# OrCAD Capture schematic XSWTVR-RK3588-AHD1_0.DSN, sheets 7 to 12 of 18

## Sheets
7 06 AHD-NVP6188A-05-08: size Custom; note: 06 AHD-NVP6188A
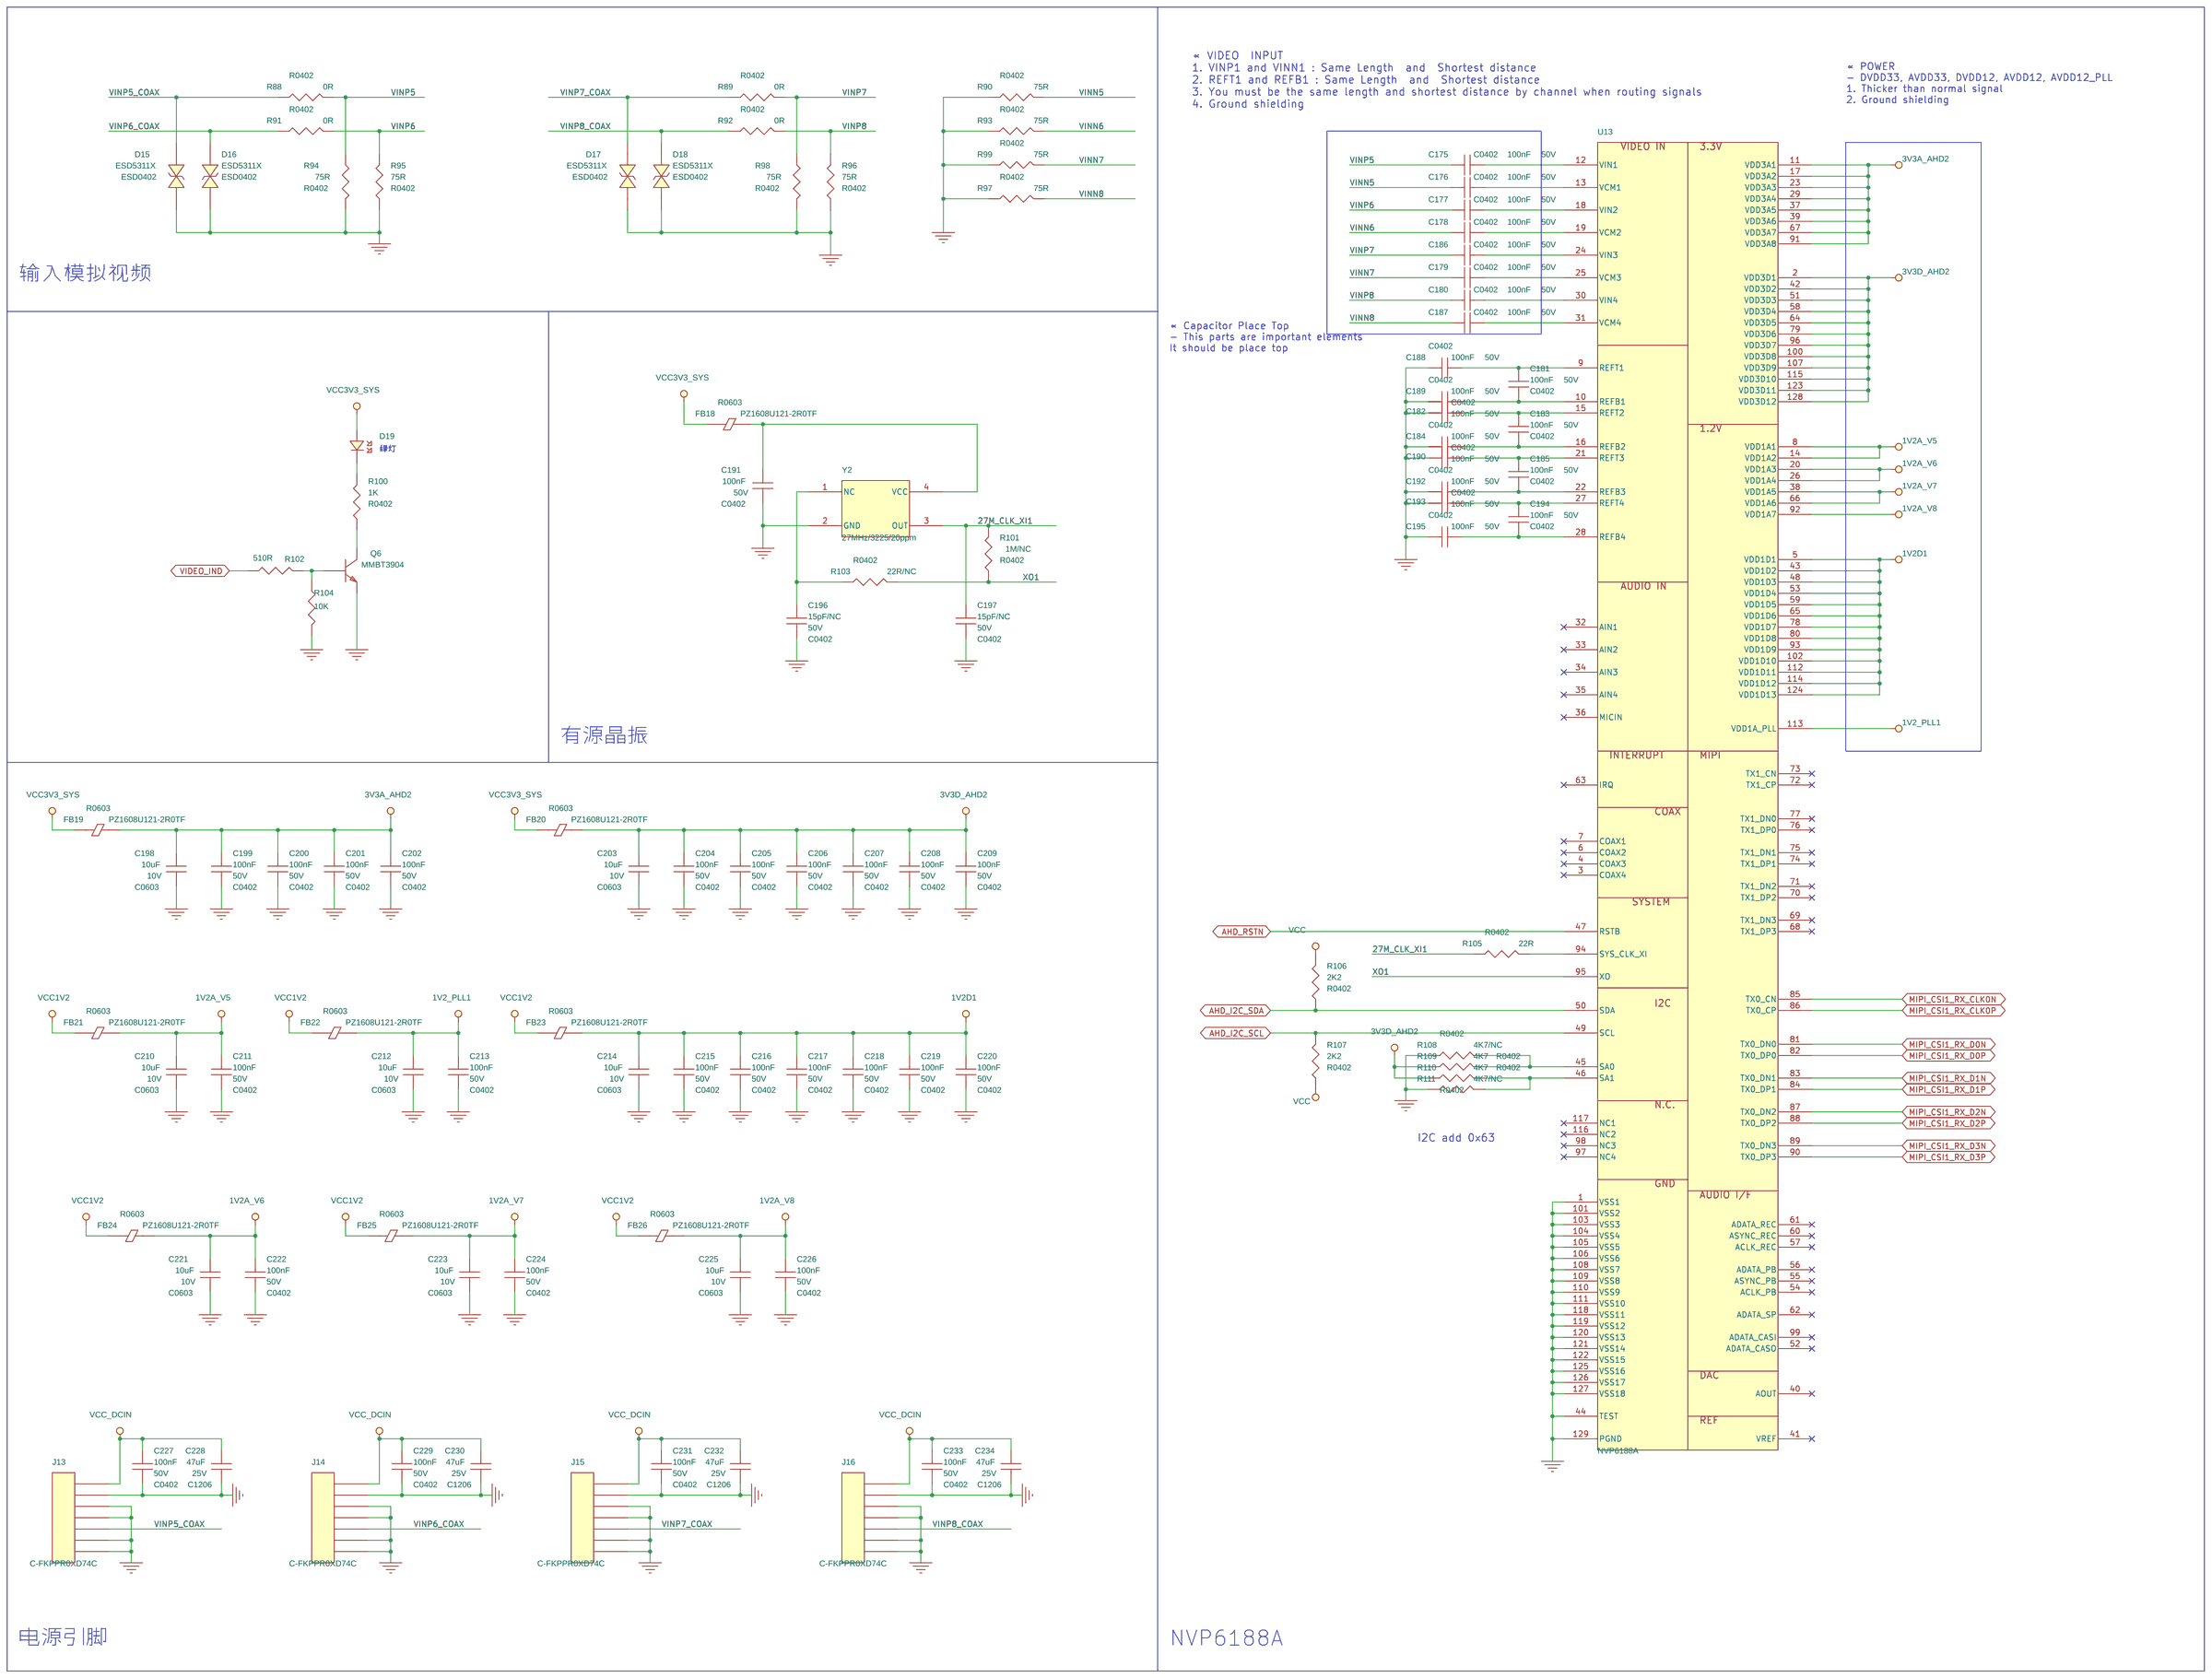
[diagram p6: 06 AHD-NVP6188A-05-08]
8 07 HDMI OUT: size A3; note: 07 HDMI OUT
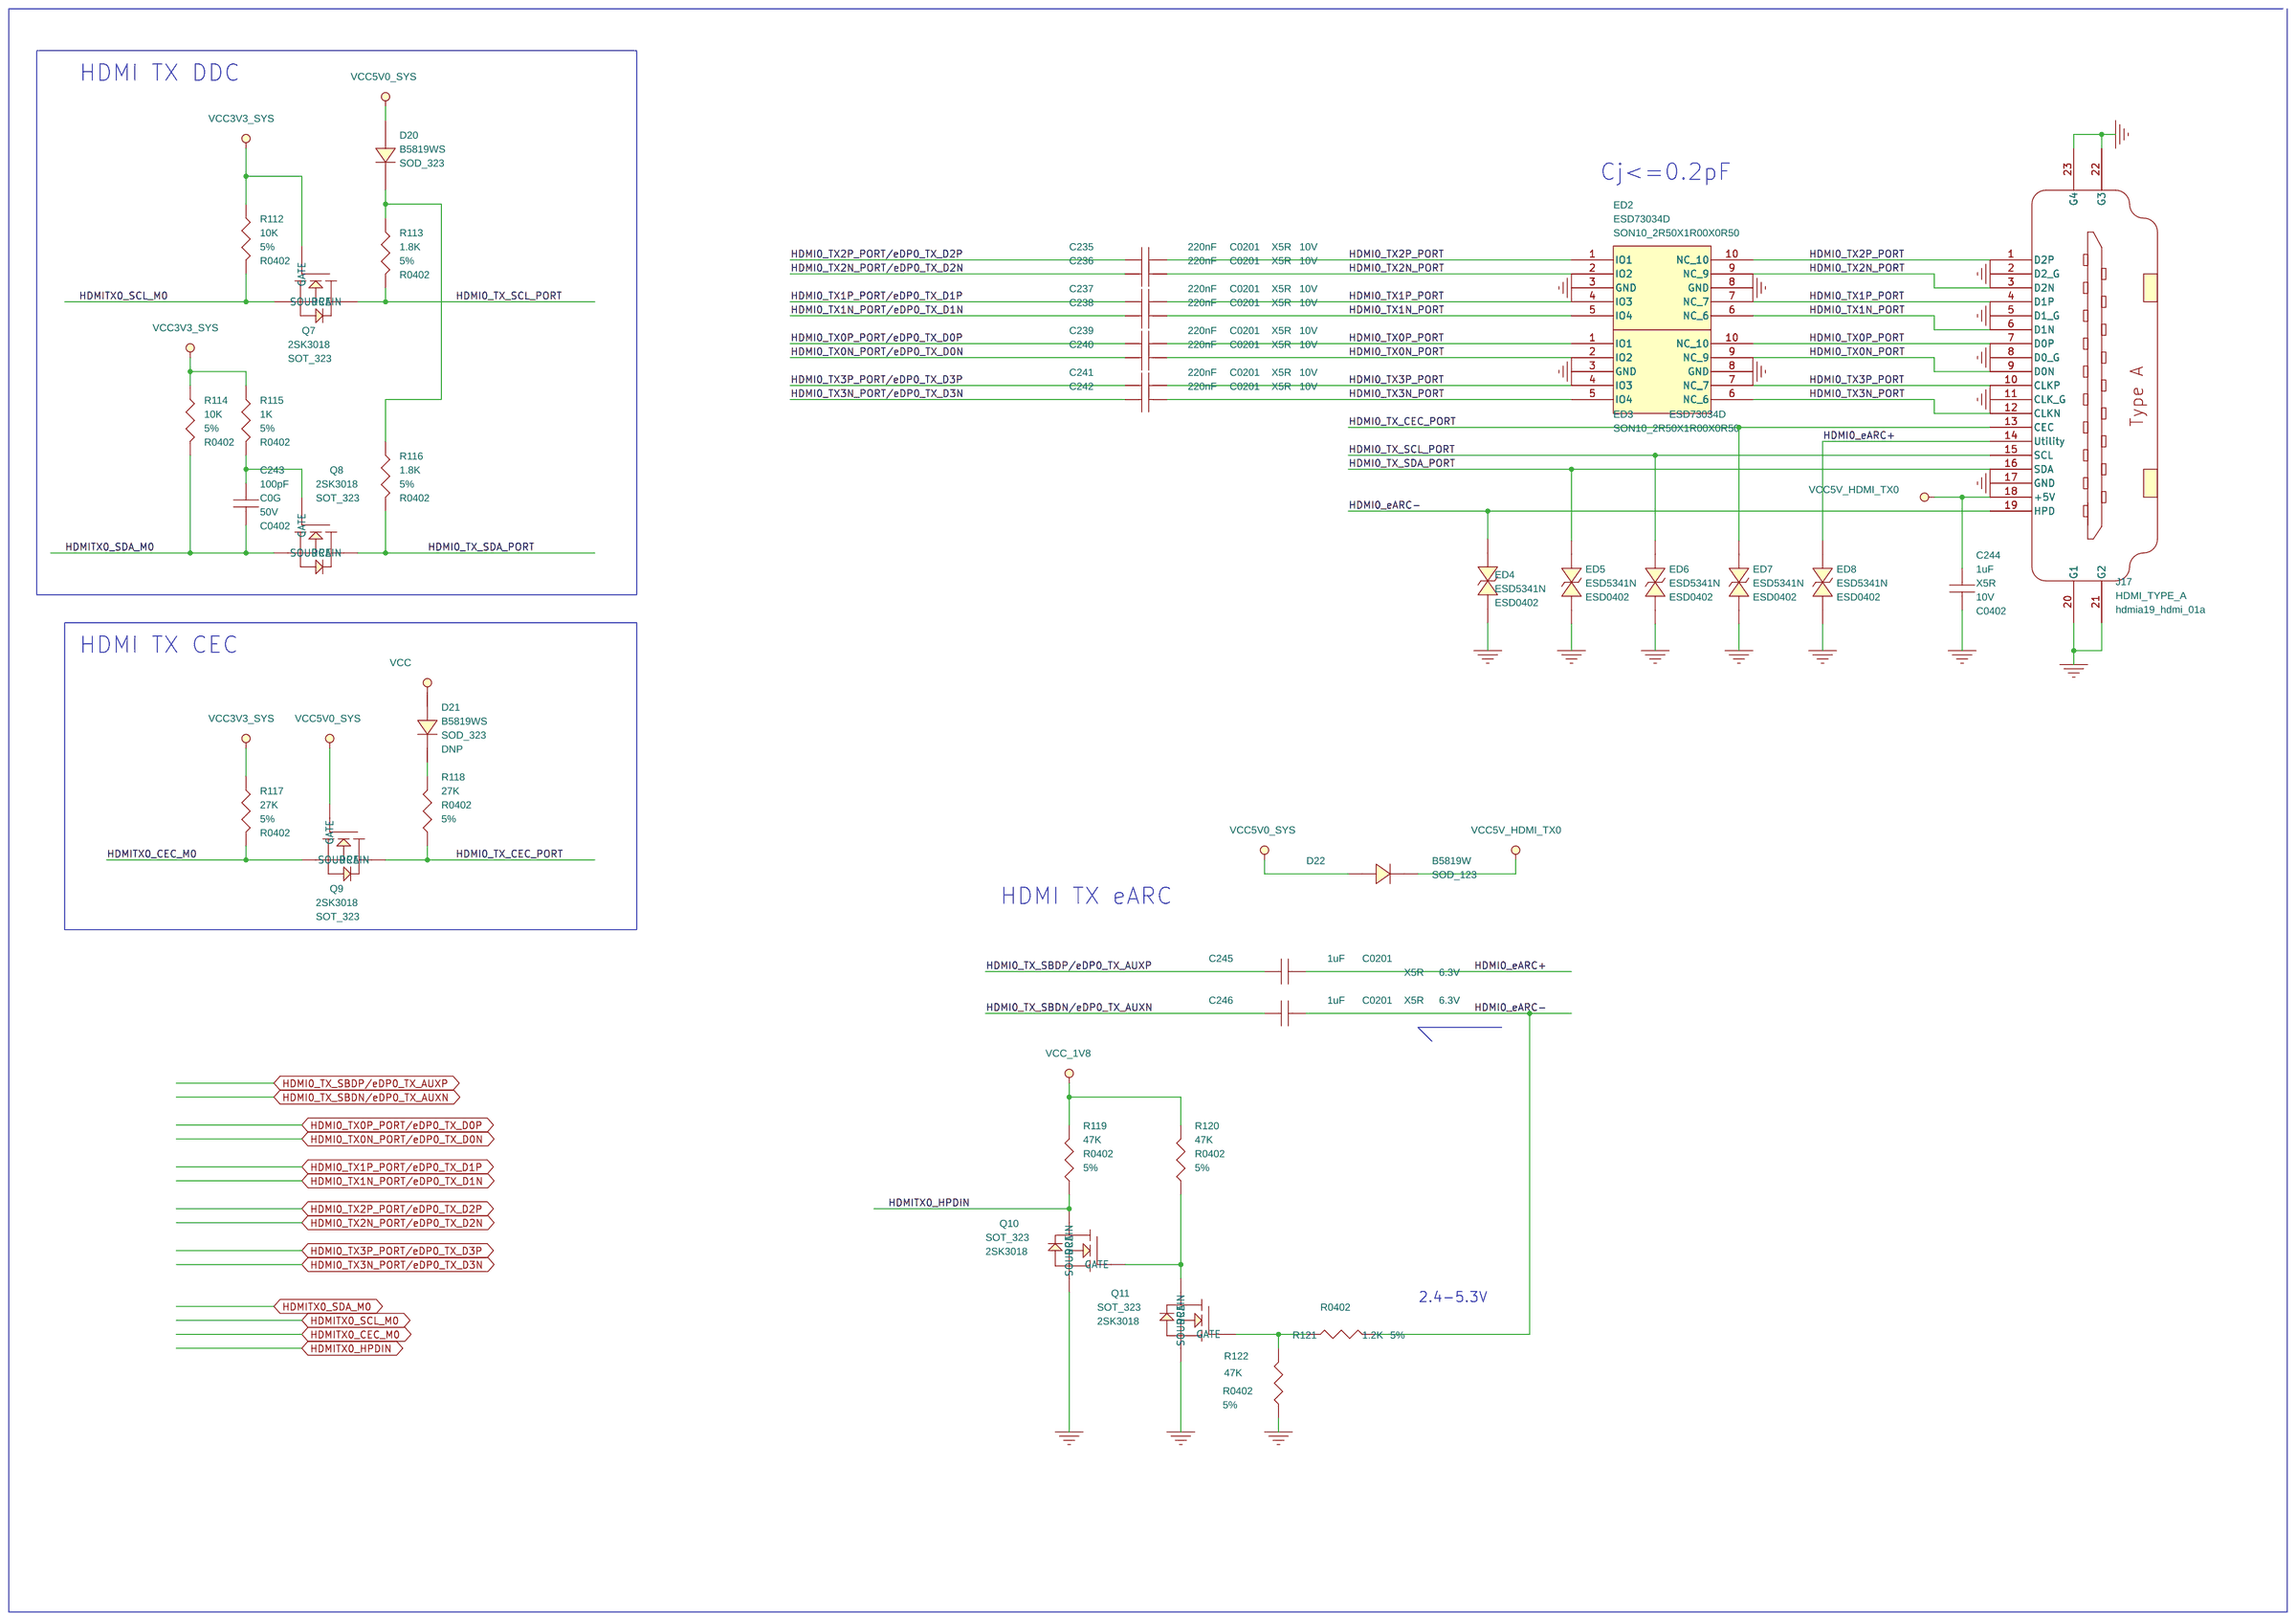
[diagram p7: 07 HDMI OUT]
9 08 WIFI6&GNSS: size Custom; note: 08 WIFI6&GNSS
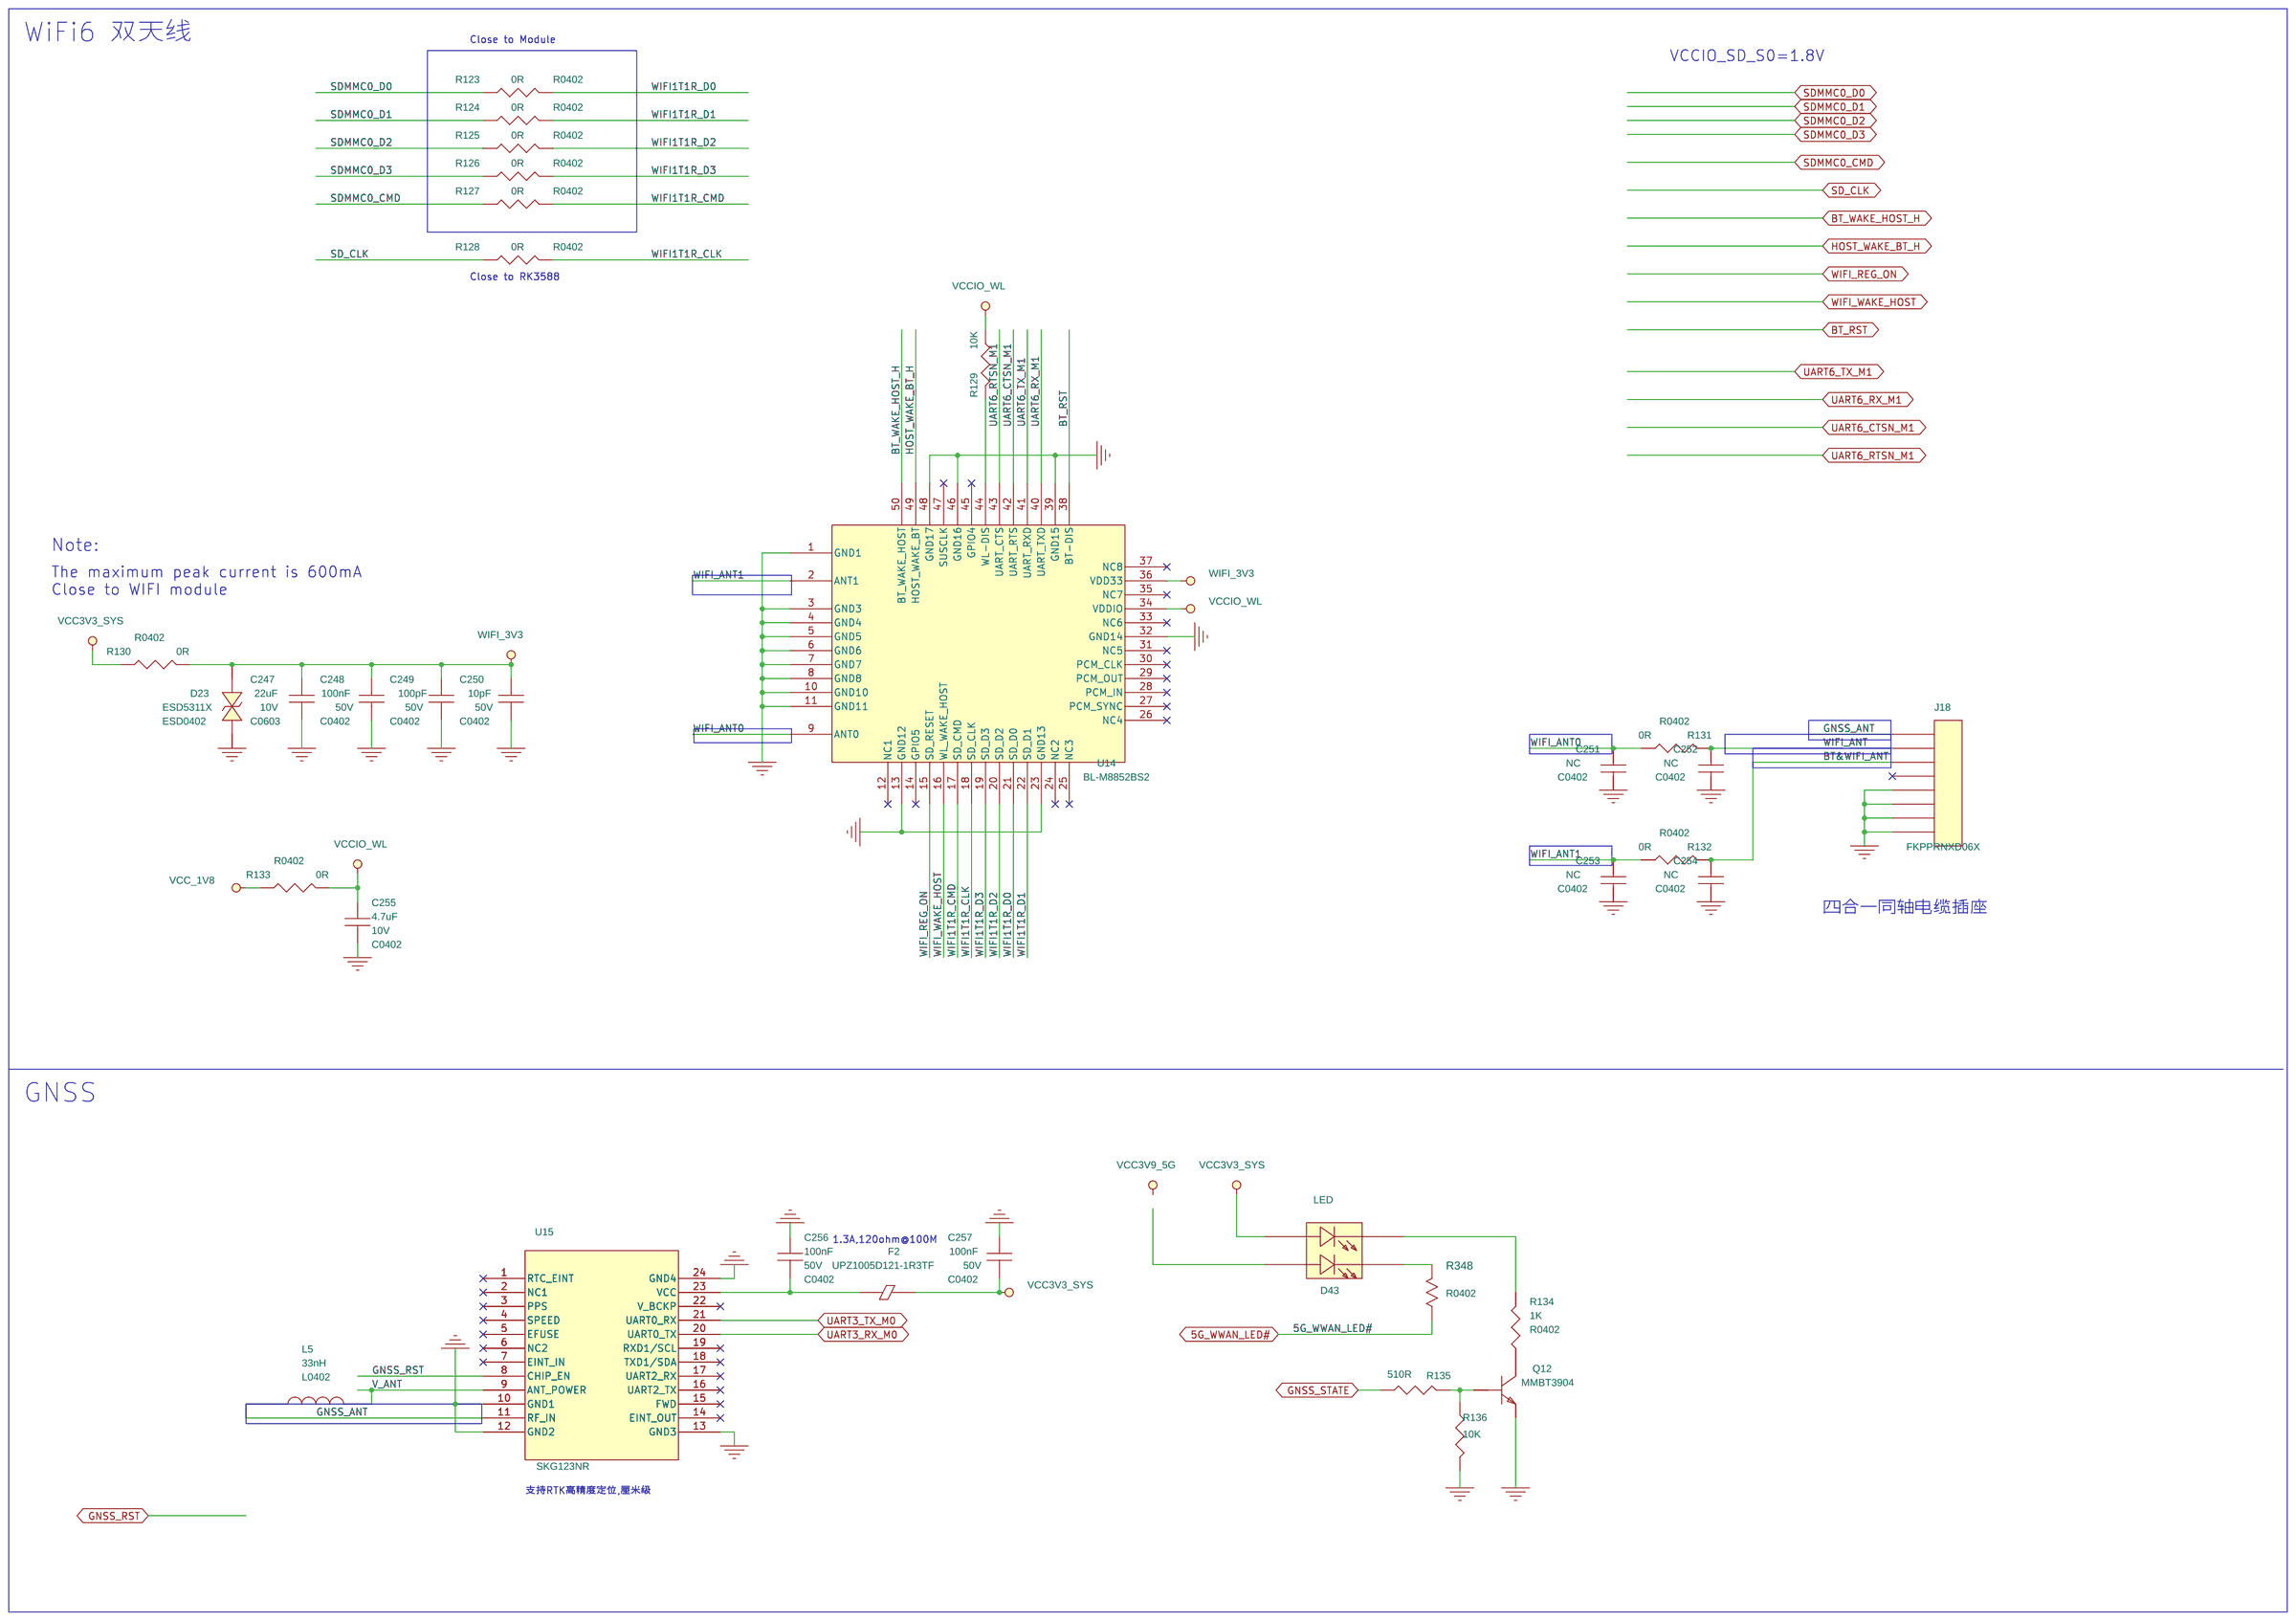
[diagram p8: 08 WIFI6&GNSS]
10 09 Ethernet-GPHY_RGMI0: size A3; rev: V1.0; note: 09 Ethernet-GPHY_RGMI0
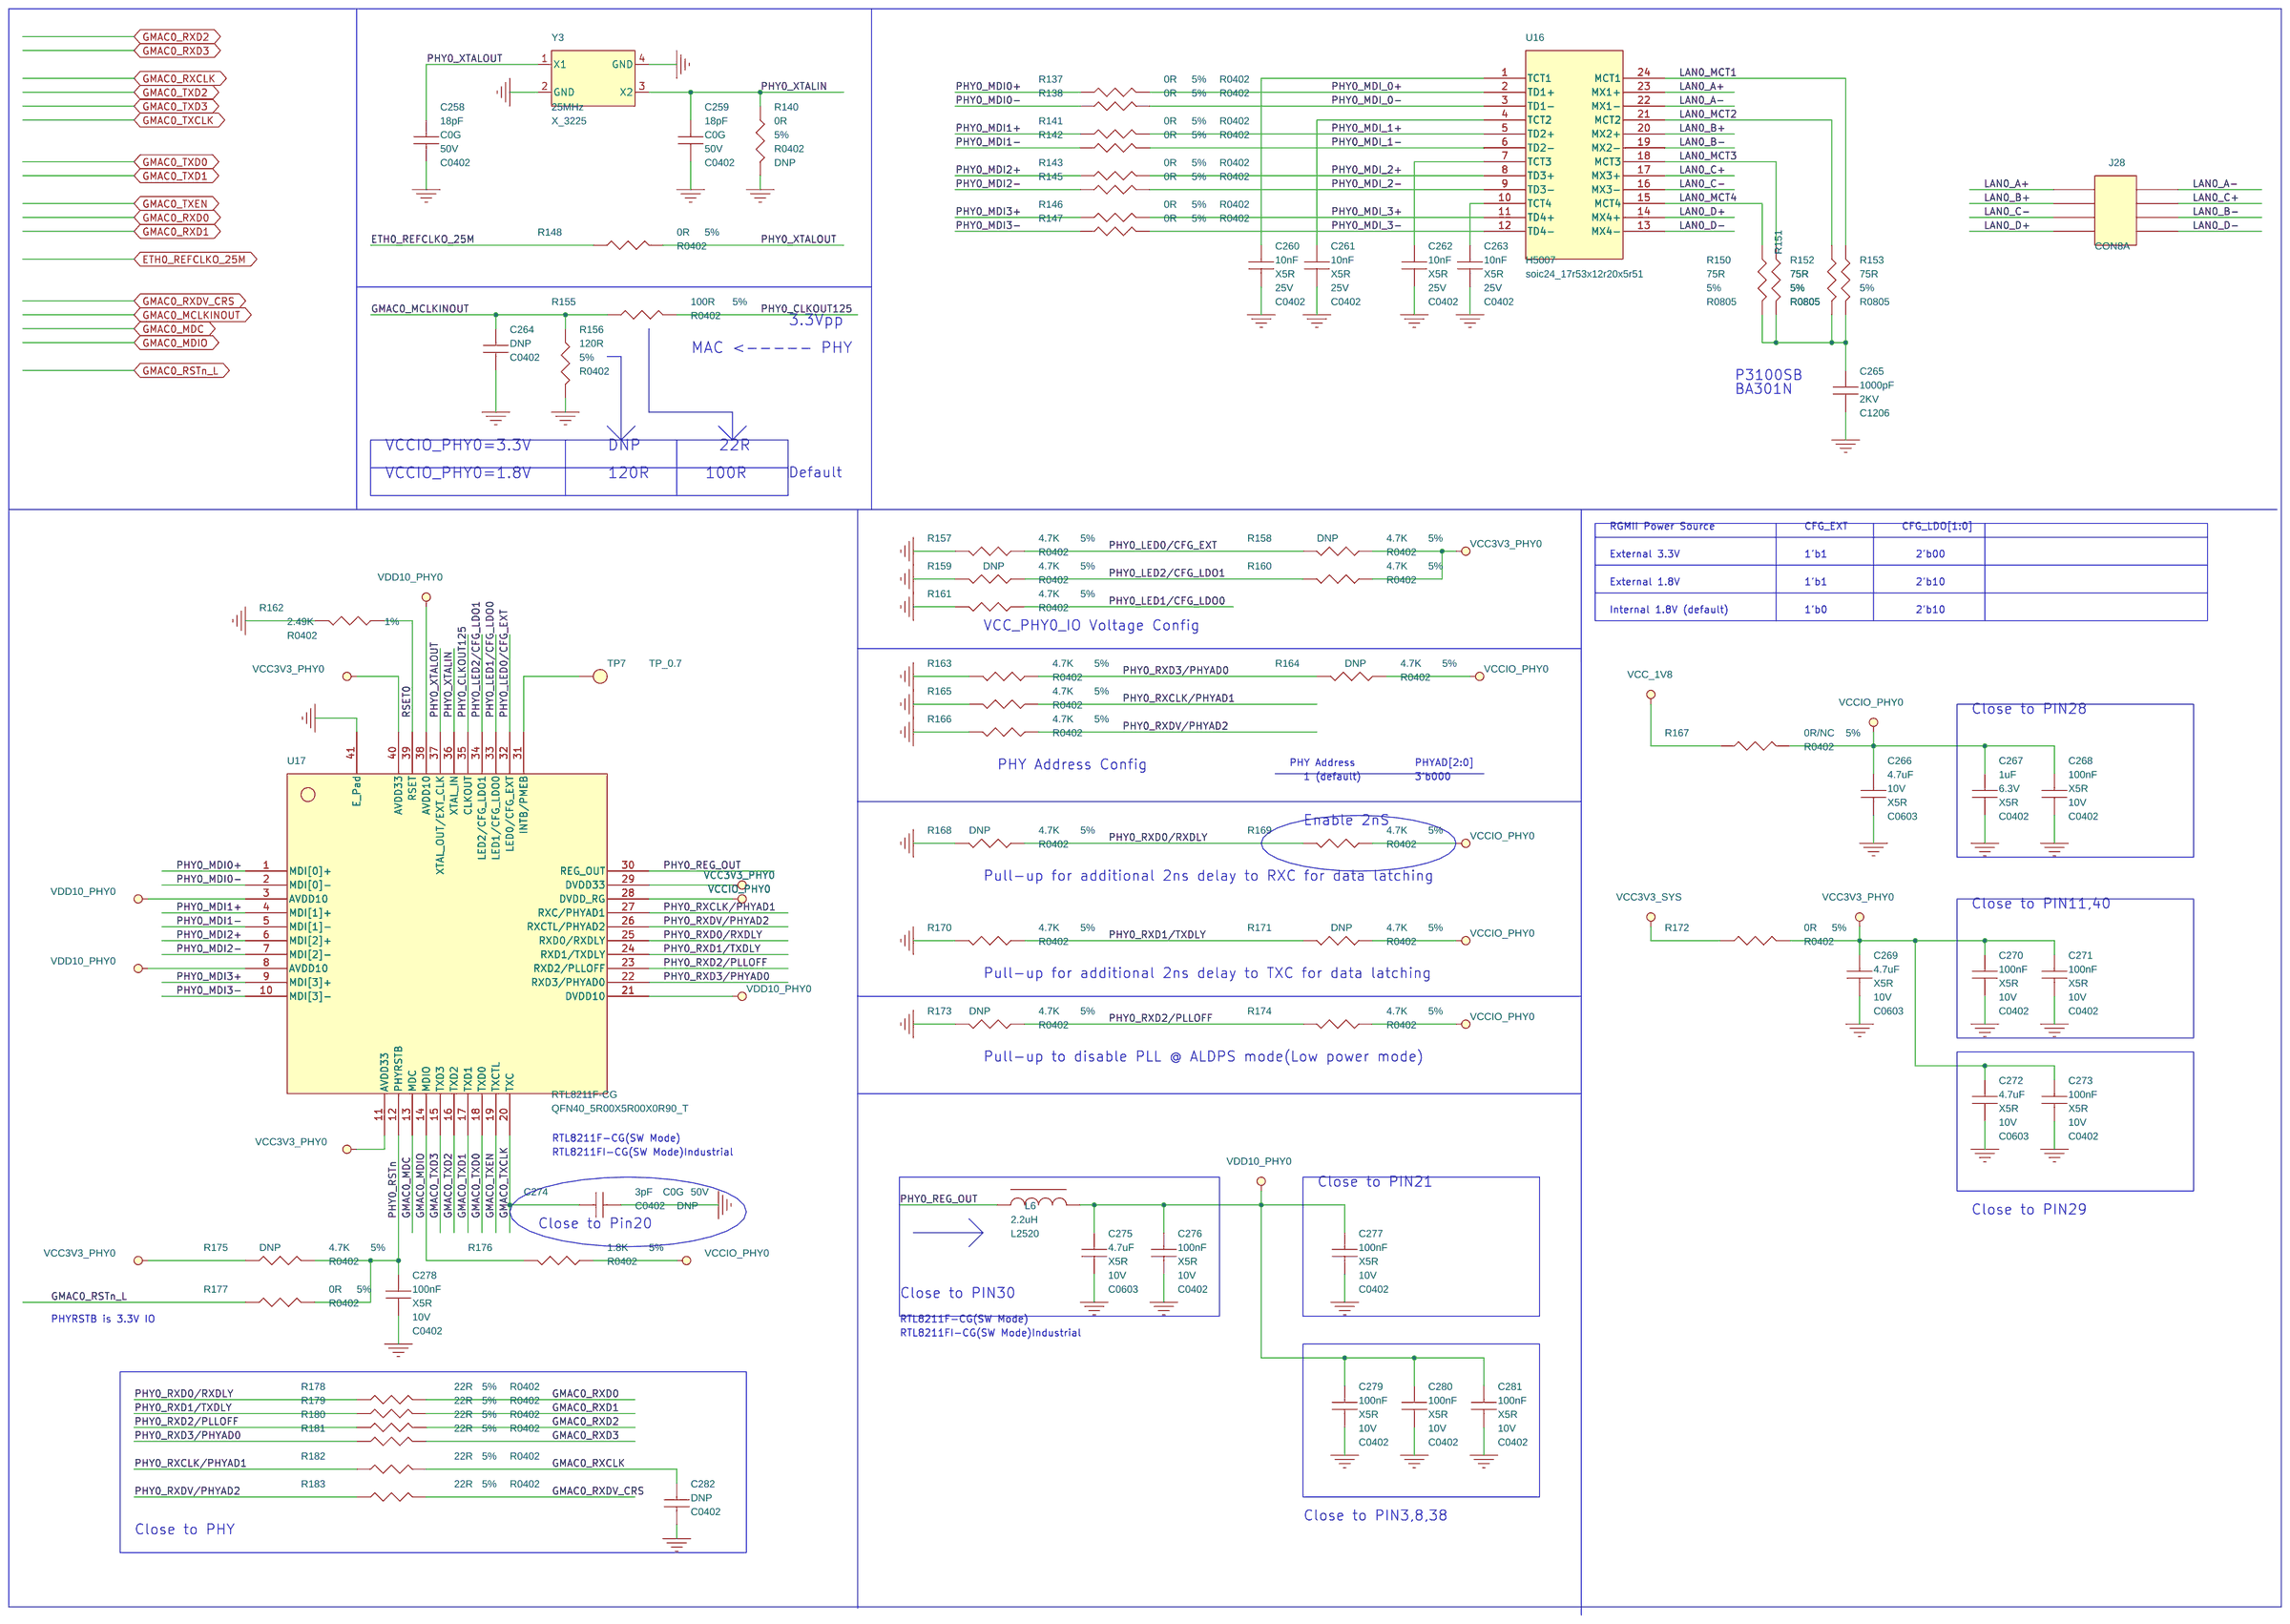
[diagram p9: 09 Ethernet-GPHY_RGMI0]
11 10 Ethernet-GPHY_RGMI1: size A3; note: 10 Ethernet-GPHY_RGMI1
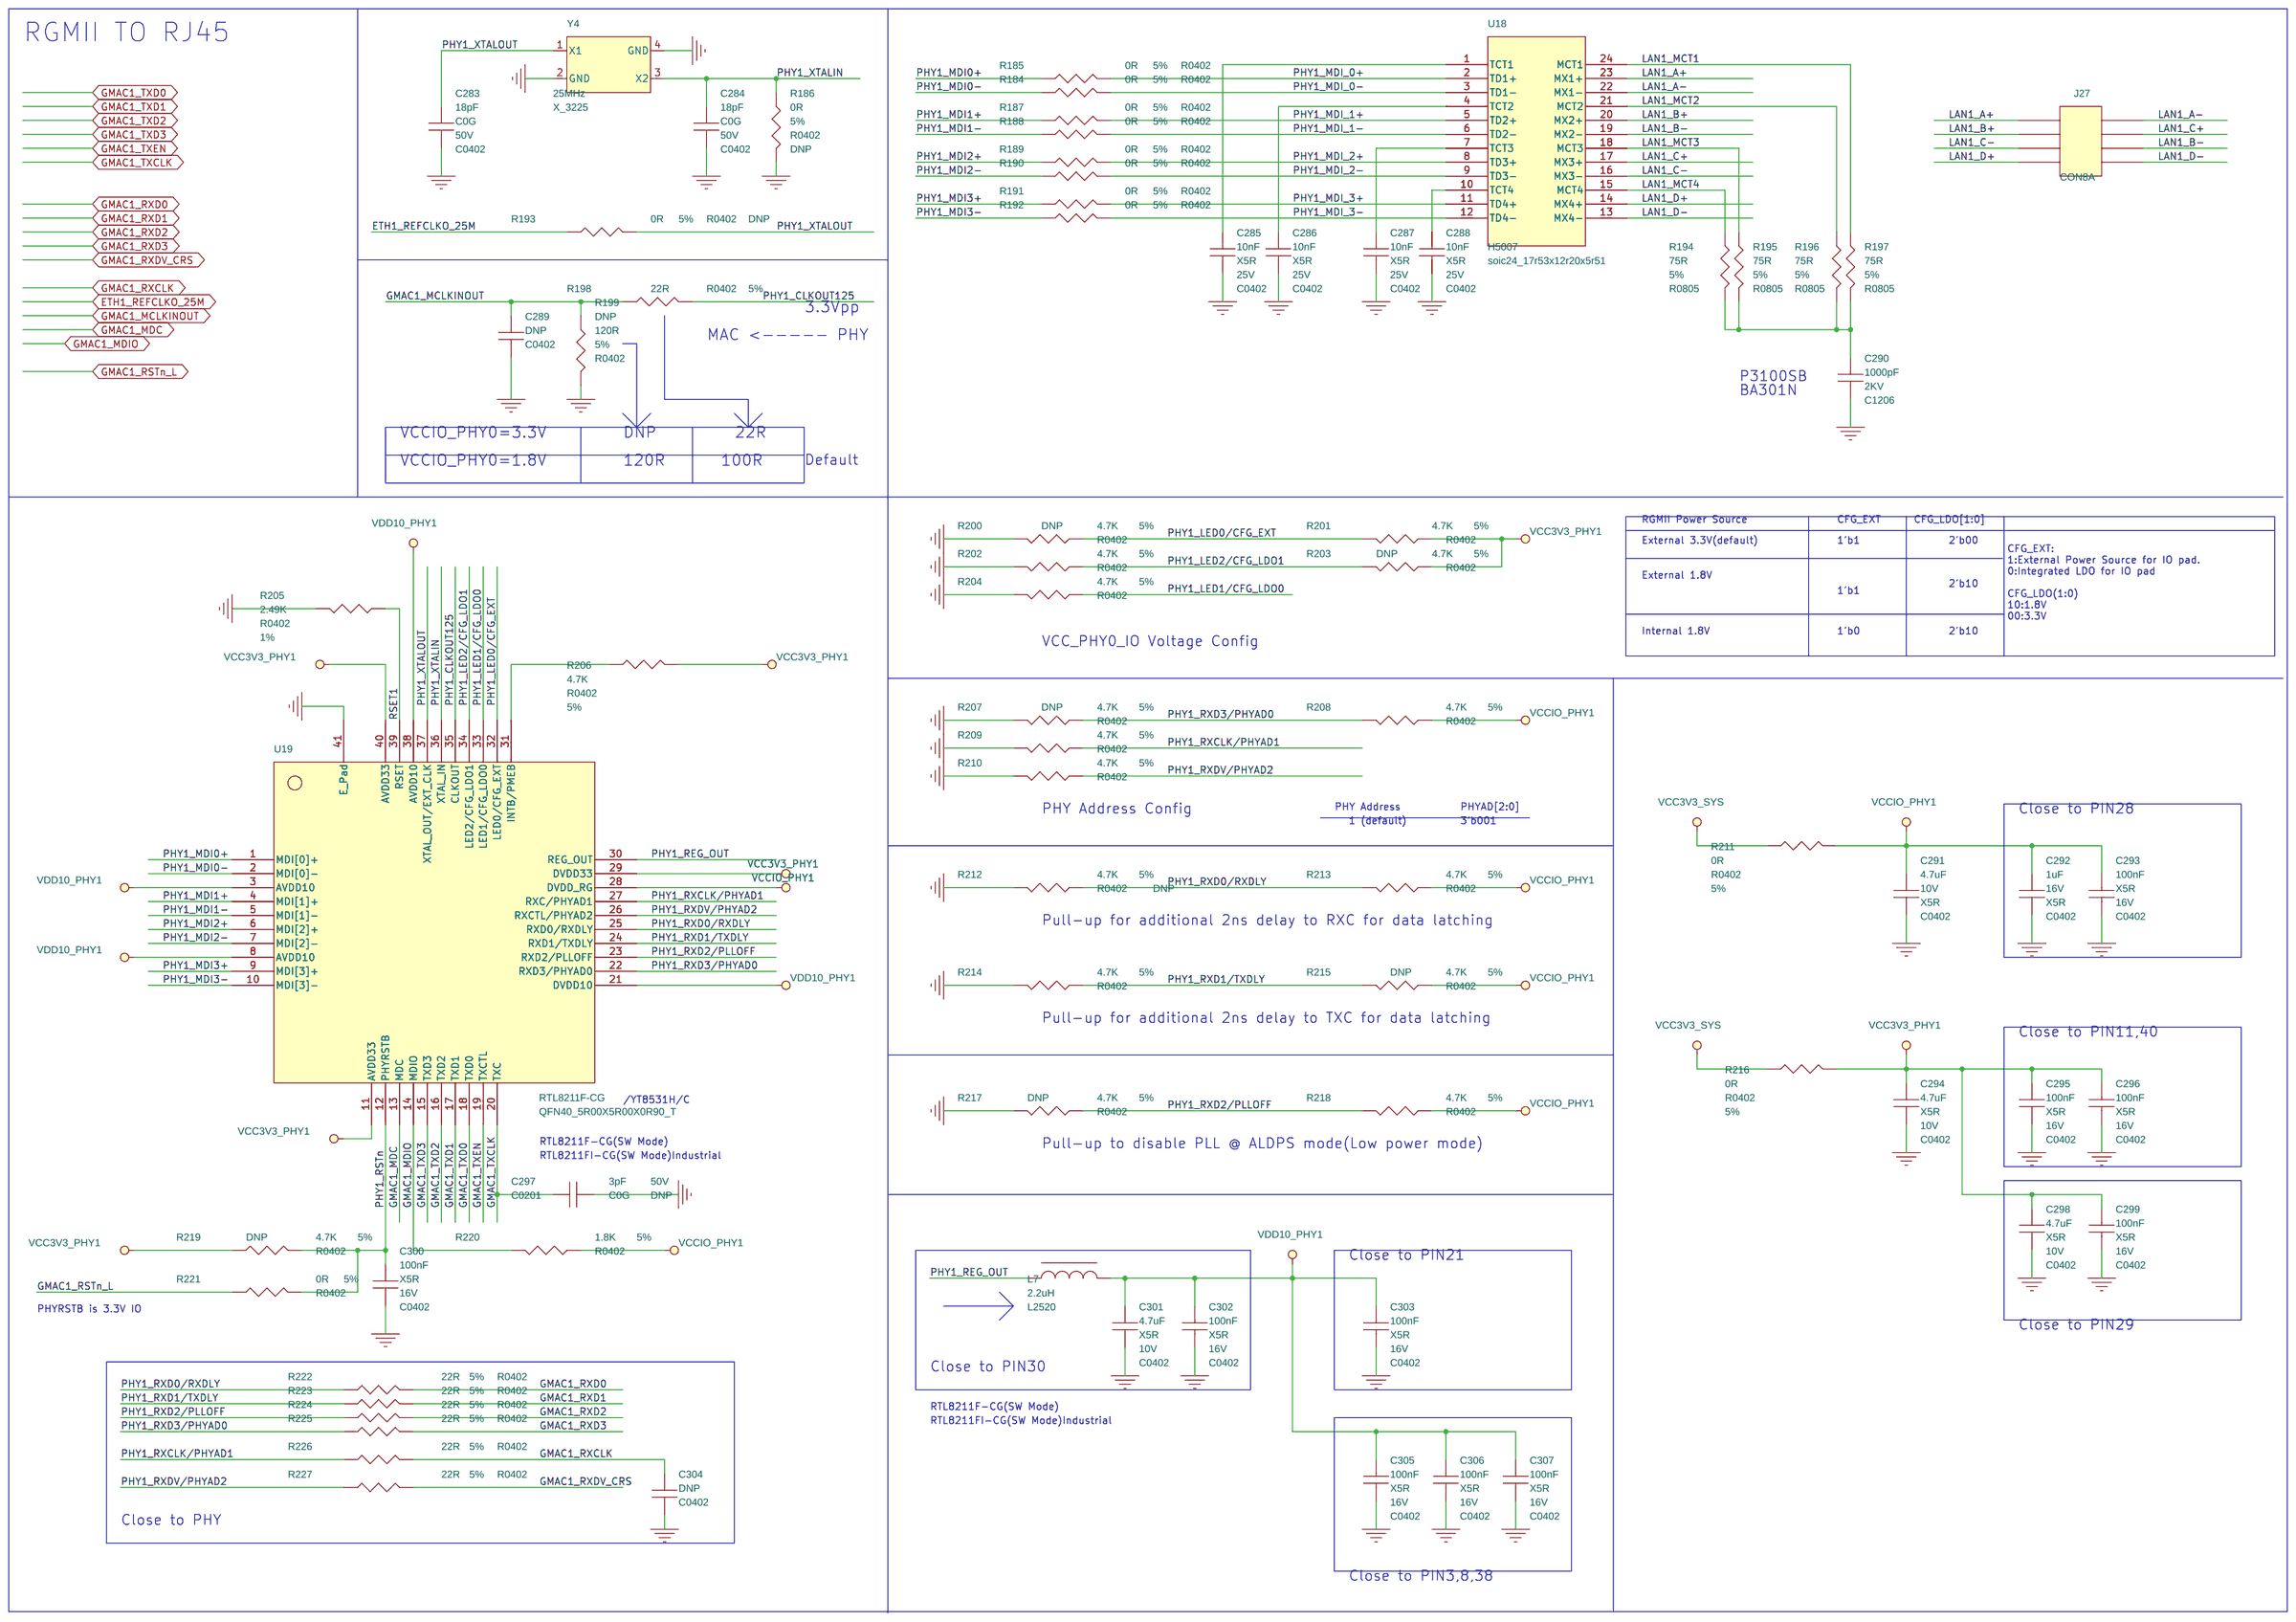
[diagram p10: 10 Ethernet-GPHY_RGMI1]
12 12 Flash-TF Card: size Custom; note: 12 Flash-TF Card
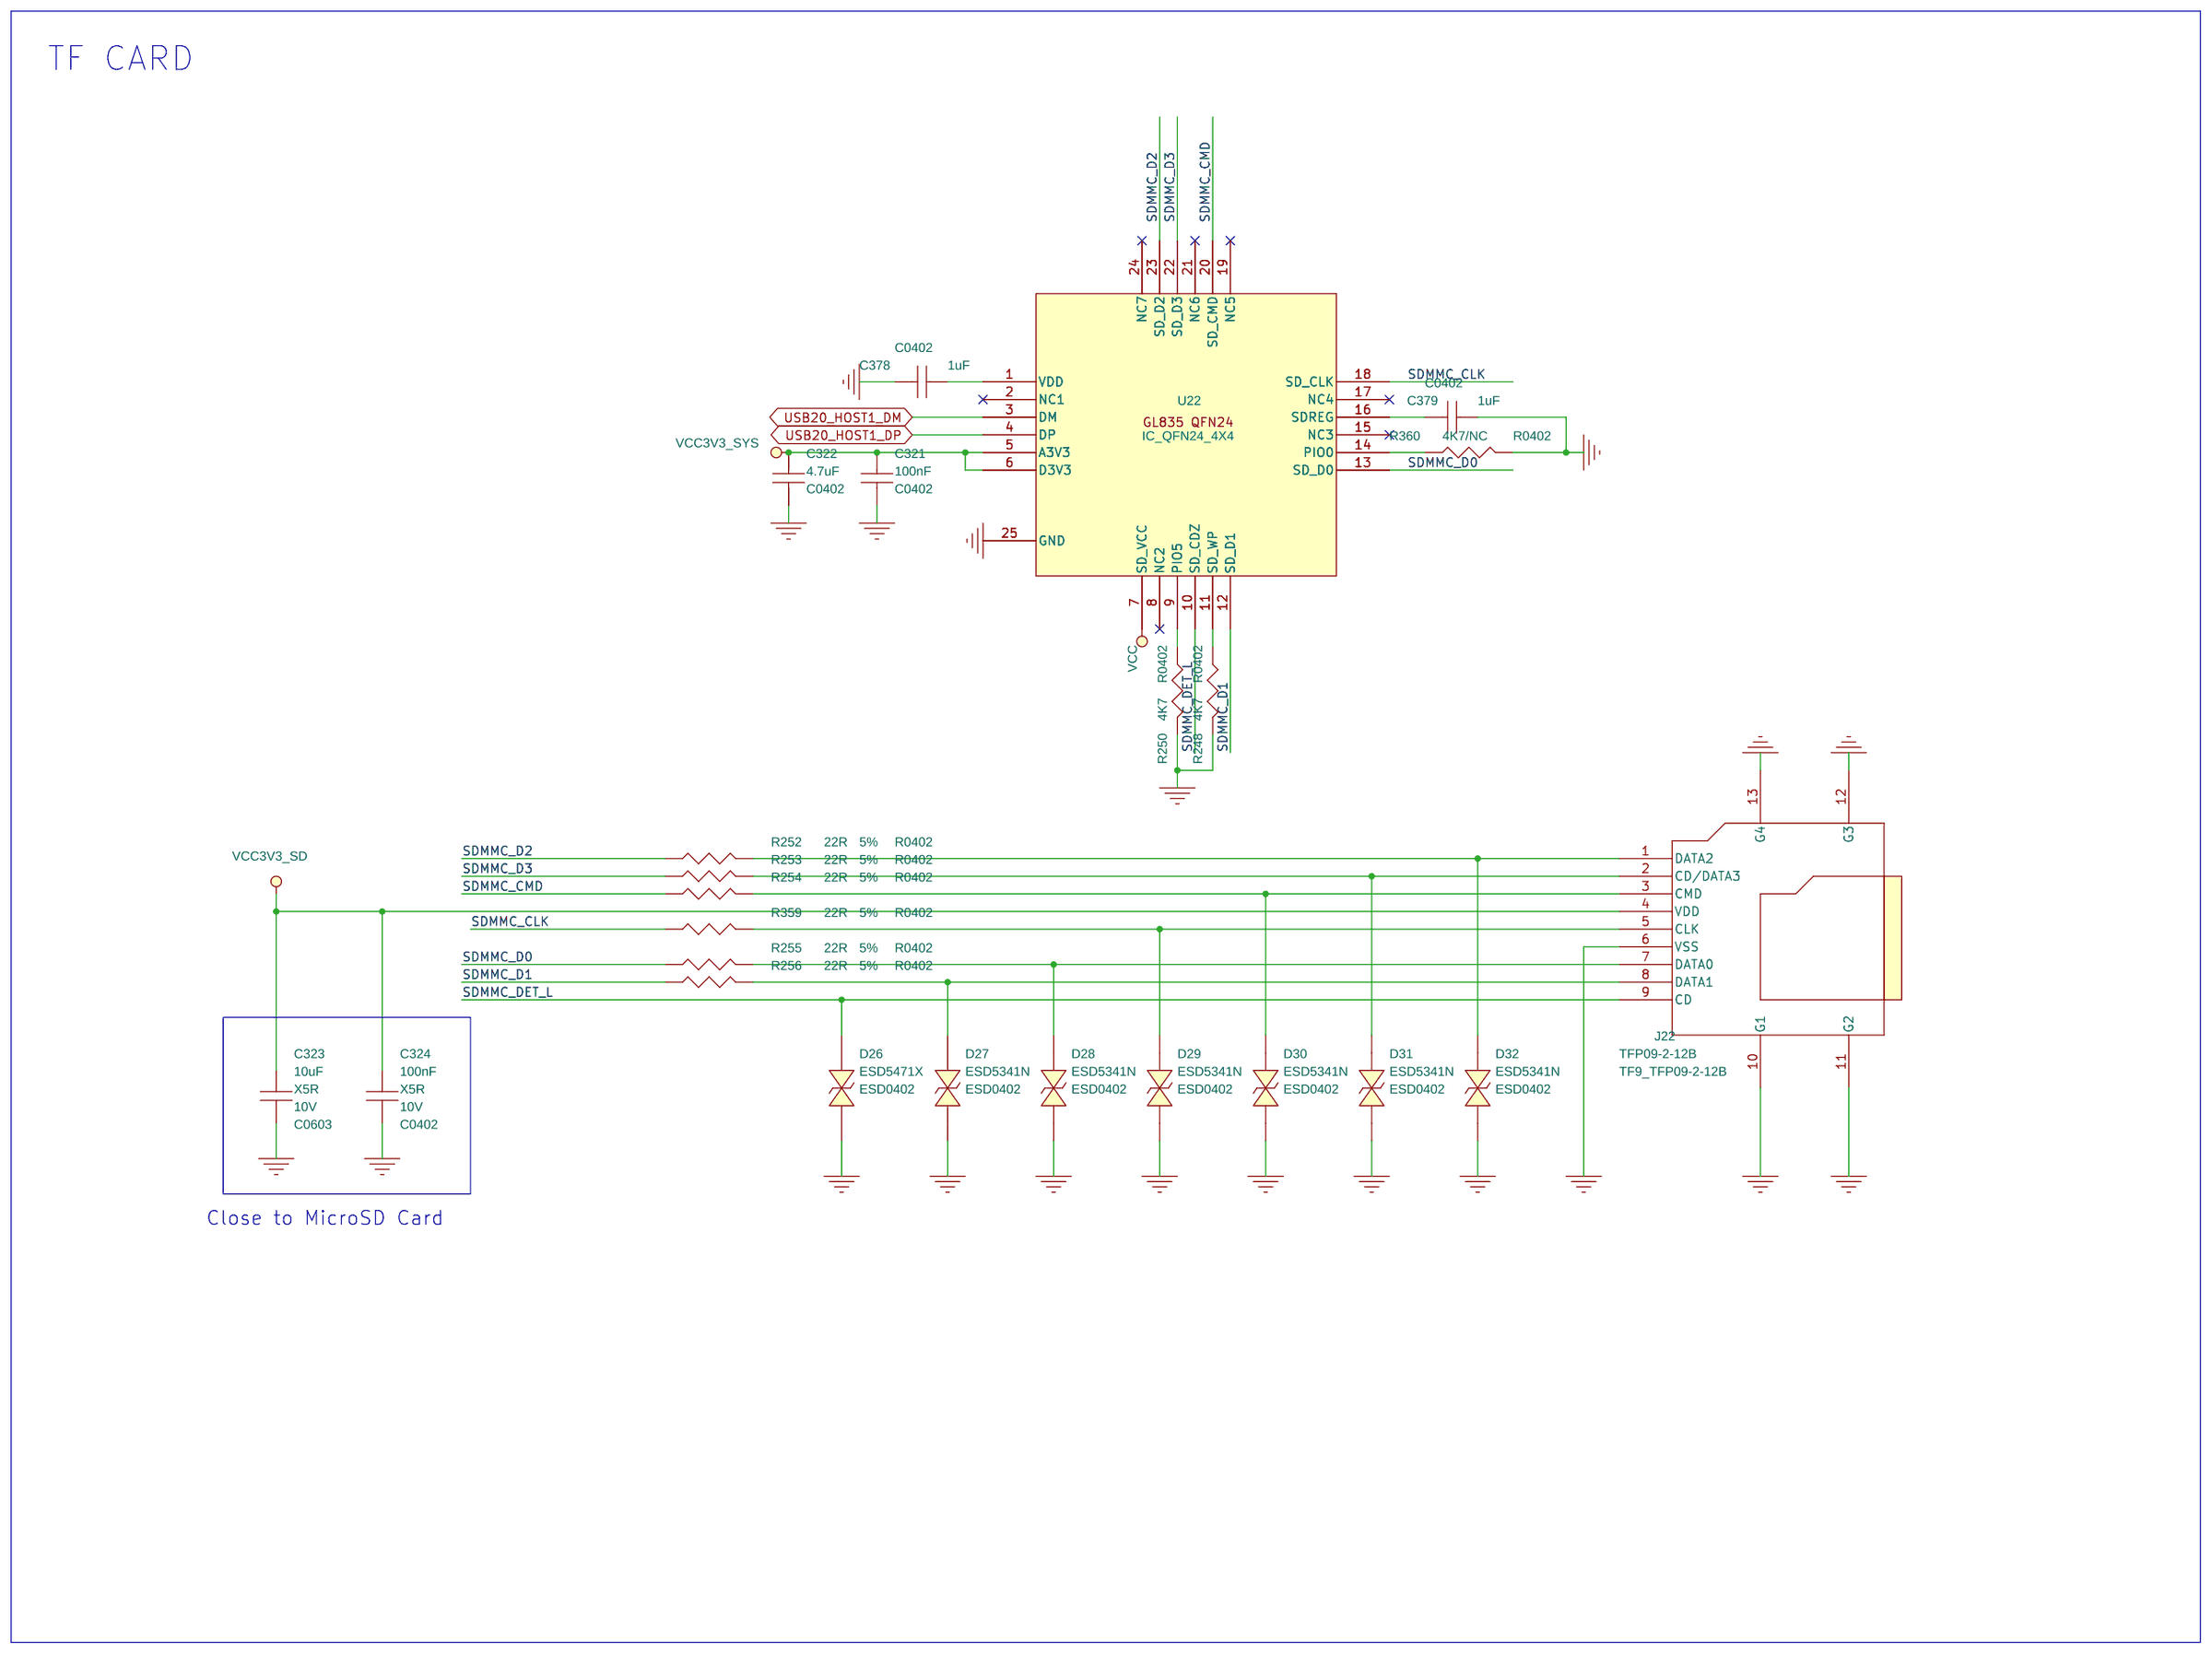
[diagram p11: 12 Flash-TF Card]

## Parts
sheet 06 AHD-NVP6188A-05-08
C175  100nF  [C0402]
C176  100nF  [C0402]
C177  100nF  [C0402]
C178  100nF  [C0402]
C179  100nF  [C0402]
C180  100nF  [C0402]
C181  100nF  [C0402]
C182  100nF  [C0402]
C183  100nF  [C0402]
C184  100nF  [C0402]
C185  100nF  [C0402]
C186  100nF  [C0402]
C187  100nF  [C0402]
C188  100nF  [C0402]
C189  100nF  [C0402]
C190  100nF  [C0402]
C191  100nF  [C0402]
C192  100nF  [C0402]
C193  100nF  [C0402]
C194  100nF  [C0402]
C195  100nF  [C0402]
C196  15pF/NC  [C0402]
C197  15pF/NC  [C0402]
C198  10uF  [C0603]
C199  100nF  [C0402]
C200  100nF  [C0402]
C201  100nF  [C0402]
C202  100nF  [C0402]
C203  10uF  [C0603]
C204  100nF  [C0402]
C205  100nF  [C0402]
C206  100nF  [C0402]
C207  100nF  [C0402]
C208  100nF  [C0402]
C209  100nF  [C0402]
C210  10uF  [C0603]
C211  100nF  [C0402]
C212  10uF  [C0603]
C213  100nF  [C0402]
C214  10uF  [C0603]
C215  100nF  [C0402]
C216  100nF  [C0402]
C217  100nF  [C0402]
C218  100nF  [C0402]
C219  100nF  [C0402]
C220  100nF  [C0402]
C221  10uF  [C0603]
C222  100nF  [C0402]
C223  10uF  [C0603]
C224  100nF  [C0402]
C225  10uF  [C0603]
C226  100nF  [C0402]
C227  100nF  [C0402]
C228  47uF  [C1206]
C229  100nF  [C0402]
C230  47uF  [C1206]
C231  100nF  [C0402]
C232  47uF  [C1206]
C233  100nF  [C0402]
C234  47uF  [C1206]
D15  ESD5311X  [ESD0402]
D16  ESD5311X  [ESD0402]
D17  ESD5311X  [ESD0402]
D18  ESD5311X  [ESD0402]
D19  GRN  [LED_0603]
FB18  PZ1608U121-2R0TF  [R0603]
FB19  PZ1608U121-2R0TF  [R0603]
FB20  PZ1608U121-2R0TF  [R0603]
FB21  PZ1608U121-2R0TF  [R0603]
FB22  PZ1608U121-2R0TF  [R0603]
FB23  PZ1608U121-2R0TF  [R0603]
FB24  PZ1608U121-2R0TF  [R0603]
FB25  PZ1608U121-2R0TF  [R0603]
FB26  PZ1608U121-2R0TF  [R0603]
J13  C-FKPPR0XD74C  [C_FKPPR0XD]
J14  C-FKPPR0XD74C  [C_FKPPR0XD]
J15  C-FKPPR0XD74C  [C_FKPPR0XD]
J16  C-FKPPR0XD74C  [C_FKPPR0XD]
Q6  MMBT3904  [SOT_23]
R88  0R  [R0402]
R89  0R  [R0402]
R90  75R  [R0402]
R91  0R  [R0402]
R92  0R  [R0402]
R93  75R  [R0402]
R94  75R  [R0402]
R95  75R  [R0402]
R96  75R  [R0402]
R97  75R  [R0402]
R98  75R  [R0402]
R99  75R  [R0402]
R100  1K  [R0402]
R101  1M/NC  [R0402]
R102  510R  [R0402]
R103  22R/NC  [R0402]
R104  10K  [R0402]
R105  22R  [R0402]
R106  2K2  [R0402]
R107  2K2  [R0402]
R108  4K7/NC  [R0402]
R109  4K7  [R0402]
R110  4K7  [R0402]
R111  4K7/NC  [R0402]
U13  NVP6188A  [IC_TQFP128]
Y2  27MHz/3225/20ppm  [X_3225]
sheet 07 HDMI OUT
C235  220nF  [C0201]
C236  220nF  [C0201]
C237  220nF  [C0201]
C238  220nF  [C0201]
C239  220nF  [C0201]
C240  220nF  [C0201]
C241  220nF  [C0201]
C242  220nF  [C0201]
C243  100pF  [C0402]
C244  1uF  [C0402]
C245  1uF  [C0201]
C246  1uF  [C0201]
D20  B5819WS  [SOD_323]
D21  B5819WS  [SOD_323]
D22  B5819W  [SOD_123]
ED2  ESD73034D  [SON10_2R50X1R00X0R50]
ED3  ESD73034D  [SON10_2R50X1R00X0R50]
ED4  ESD5341N  [ESD0402]
ED5  ESD5341N  [ESD0402]
ED6  ESD5341N  [ESD0402]
ED7  ESD5341N  [ESD0402]
ED8  ESD5341N  [ESD0402]
J17  HDMI_TYPE_A  [hdmia19_hdmi_01a]
Q7  2SK3018  [SOT_323]
Q8  2SK3018  [SOT_323]
Q9  2SK3018  [SOT_323]
Q10  2SK3018  [SOT_323]
Q11  2SK3018  [SOT_323]
R112  10K  [R0402]
R113  1.8K  [R0402]
R114  10K  [R0402]
R115  1K  [R0402]
R116  1.8K  [R0402]
R117  27K  [R0402]
R118  27K  [R0402]
R119  47K  [R0402]
R120  47K  [R0402]
R121  1.2K  [R0402]
R122  47K  [R0402]
sheet 08 WIFI6&GNSS
C247  22uF  [C0603]
C248  100nF  [C0402]
C249  100pF  [C0402]
C250  10pF  [C0402]
C251  NC  [C0402]
C252  NC  [C0402]
C253  NC  [C0402]
C254  NC  [C0402]
C255  4.7uF  [C0402]
C256  100nF  [C0402]
C257  100nF  [C0402]
D23  ESD5311X  [ESD0402]
D43  LED  [LEDX2]
F2  UPZ1005D121-1R3TF  [R0402]
J18  FKPPRNXD06X  [FKPPRNXD06X]
L5  33nH  [L0402]
Q12  MMBT3904  [SOT_23]
R123  0R  [R0402]
R124  0R  [R0402]
R125  0R  [R0402]
R126  0R  [R0402]
R127  0R  [R0402]
R128  0R  [R0402]
R129  10K  [R0402]
R130  0R  [R0402]
R131  0R  [R0402]
R132  0R  [R0402]
R133  0R  [R0402]
R134  1K  [R0402]
R135  510R  [R0402]
R136  10K  [R0402]
R348  1K  [R0402]
U14  BL-M8852BS2  [IC_BL_M8852BS2]
U15  SKG123NR  [MODEL_SKG123NR]
sheet 09 Ethernet-GPHY_RGMI0
C258  18pF  [C0402]
C259  18pF  [C0402]
C260  10nF  [C0402]
C261  10nF  [C0402]
C262  10nF  [C0402]
C263  10nF  [C0402]
C264  DNP  [C0402]
C265  1000pF  [C1206]
C266  4.7uF  [C0603]
C267  1uF  [C0402]
C268  100nF  [C0402]
C269  4.7uF  [C0603]
C270  100nF  [C0402]
C271  100nF  [C0402]
C272  4.7uF  [C0603]
C273  100nF  [C0402]
C274  3pF  [C0402]
C275  4.7uF  [C0603]
C276  100nF  [C0402]
C277  100nF  [C0402]
C278  100nF  [C0402]
C279  100nF  [C0402]
C280  100nF  [C0402]
C281  100nF  [C0402]
C282  DNP  [C0402]
J28  CON8A  [SOCKET_2x4_2p54mm]
L6  2.2uH  [L2520]
R137  0R  [R0402]
R138  0R  [R0402]
R140  0R  [R0402]
R141  0R  [R0402]
R142  0R  [R0402]
R143  0R  [R0402]
R145  0R  [R0402]
R146  0R  [R0402]
R147  0R  [R0402]
R148  0R  [R0402]
R150  75R  [R0805]
R151  75R  [R0805]
R152  75R  [R0805]
R153  75R  [R0805]
R155  100R  [R0402]
R156  120R  [R0402]
R157  4.7K  [R0402]
R158  4.7K  [R0402]
R159  4.7K  [R0402]
R160  4.7K  [R0402]
R161  4.7K  [R0402]
R162  2.49K  [R0402]
R163  4.7K  [R0402]
R164  4.7K  [R0402]
R165  4.7K  [R0402]
R166  4.7K  [R0402]
R167  0R/NC  [R0402]
R168  4.7K  [R0402]
R169  4.7K  [R0402]
R170  4.7K  [R0402]
R171  4.7K  [R0402]
R172  0R  [R0402]
R173  4.7K  [R0402]
R174  4.7K  [R0402]
R175  4.7K  [R0402]
R176  1.8K  [R0402]
R177  0R  [R0402]
R178  22R  [R0402]
R179  22R  [R0402]
R180  22R  [R0402]
R181  22R  [R0402]
R182  22R  [R0402]
R183  22R  [R0402]
TP7  TP_0.7  [TP_0R70]
U16  H5007  [soic24_17r53x12r20x5r51]
U17  RTL8211F-CG  [QFN40_5R00X5R00X0R90_T]
Y3  25MHz  [X_3225]
sheet 10 Ethernet-GPHY_RGMI1
C283  18pF  [C0402]
C284  18pF  [C0402]
C285  10nF  [C0402]
C286  10nF  [C0402]
C287  10nF  [C0402]
C288  10nF  [C0402]
C289  DNP  [C0402]
C290  1000pF  [C1206]
C291  4.7uF  [C0402]
C292  1uF  [C0402]
C293  100nF  [C0402]
C294  4.7uF  [C0402]
C295  100nF  [C0402]
C296  100nF  [C0402]
C297  3pF  [C0201]
C298  4.7uF  [C0402]
C299  100nF  [C0402]
C300  100nF  [C0402]
C301  4.7uF  [C0402]
C302  100nF  [C0402]
C303  100nF  [C0402]
C304  DNP  [C0402]
C305  100nF  [C0402]
C306  100nF  [C0402]
C307  100nF  [C0402]
J27  CON8A  [SOCKET_2x4_2p54mm]
L7  2.2uH  [L2520]
R184  0R  [R0402]
R185  0R  [R0402]
R186  0R  [R0402]
R187  0R  [R0402]
R188  0R  [R0402]
R189  0R  [R0402]
R190  0R  [R0402]
R191  0R  [R0402]
R192  0R  [R0402]
R193  0R  [R0402]
R194  75R  [R0805]
R195  75R  [R0805]
R196  75R  [R0805]
R197  75R  [R0805]
R198  22R  [R0402]
R199  120R  [R0402]
R200  4.7K  [R0402]
R201  4.7K  [R0402]
R202  4.7K  [R0402]
R203  4.7K  [R0402]
R204  4.7K  [R0402]
R205  2.49K  [R0402]
R206  4.7K  [R0402]
R207  4.7K  [R0402]
R208  4.7K  [R0402]
R209  4.7K  [R0402]
R210  4.7K  [R0402]
R211  0R  [R0402]
R212  4.7K  [R0402]
R213  4.7K  [R0402]
R214  4.7K  [R0402]
R215  4.7K  [R0402]
R216  0R  [R0402]
R217  4.7K  [R0402]
R218  4.7K  [R0402]
R219  4.7K  [R0402]
R220  1.8K  [R0402]
R221  0R  [R0402]
R222  22R  [R0402]
R223  22R  [R0402]
R224  22R  [R0402]
R225  22R  [R0402]
R226  22R  [R0402]
R227  22R  [R0402]
U18  H5007  [soic24_17r53x12r20x5r51]
U19  RTL8211F-CG  [QFN40_5R00X5R00X0R90_T]
Y4  25MHz  [X_3225]
sheet 12 Flash-TF Card
C321  100nF  [C0402]
C322  4.7uF  [C0402]
C323  10uF  [C0603]
C324  100nF  [C0402]
C378  1uF  [C0402]
C379  1uF  [C0402]
D26  ESD5471X  [ESD0402]
D27  ESD5341N  [ESD0402]
D28  ESD5341N  [ESD0402]
D29  ESD5341N  [ESD0402]
D30  ESD5341N  [ESD0402]
D31  ESD5341N  [ESD0402]
D32  ESD5341N  [ESD0402]
J22  TFP09-2-12B  [TF9_TFP09-2-12B]
R248  4K7  [R0402]
R250  4K7  [R0402]
R252  22R  [R0402]
R253  22R  [R0402]
R254  22R  [R0402]
R255  22R  [R0402]
R256  22R  [R0402]
R359  22R  [R0402]
R360  4K7/NC  [R0402]
U22  GL835-QFN24-4X4  [IC_QFN24_4X4]

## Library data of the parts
C175-C195 = CAP_NP_2: cap,100.00nF,+/-10%,10V,X5R,C0402; C_Voltage: 6.3V; Created by: JJJ; Dielectric: X5R; Manufacturer: TDK; Manufacturer PN: C1005X5R1A104K050BA; Number: 37; Priority: A; RK PN: C1005X5R1A104K050BA; Tolerance: 10%; Voltage: 50V
C196 C197 C249 C250 = CAP_NP_0: cap,18.00pF,+/-5%,50V,C0G,C0402; C_Voltage: 6.3V; Created by: JJJ; Dielectric: C0G; Manufacturer: TDK; Manufacturer PN: C1005C0G1H180J050BA; Number: 37; Priority: A; RK PN: C1005C0G1H180J050BA; Tolerance: 5%; Voltage: 50V
C198 C203 C210 C212 C214 C221 C223 C225 = CAP_NP_0: cap,10.00uF,+/-10%,25V,X5R,C1206; C_Voltage: 6.3V; Created by: JJJ; Dielectric: X5R; Manufacturer: TDK; Manufacturer PN: C3216X5R1E106K085AC; Part Type: C1206; Priority: A; RK PN: C3216X5R1E106K085AC; Tolerance: 10%; Voltage: 10V
C199-C202 C204-C209 C211 C213 C215-C220 C222 C224 C226 = CAP_NP_0: cap,10.00uF,+/-10%,25V,X5R,C1206; C_Voltage: 6.3V; Created by: JJJ; Dielectric: X5R; Manufacturer: TDK; Manufacturer PN: C3216X5R1E106K085AC; Part Type: C1206; Priority: A; RK PN: C3216X5R1E106K085AC; Tolerance: 10%; Voltage: 50V
C227 C229 C231 C233 = CAP_NP_11: cap,100.00nF,+/-10%,50V,X5R,C0603; Created by: JJJ; Dielectric: X5R; Manufacturer: TDK; Manufacturer PN: C1608X5R1H104K080AA; Part Type: C0603; Priority: A; RK PN: C1608X5R1H104K080AA; Tolerance: 10%; Voltage: 50V
C228 C230 C232 C234 = CAP_NP_0: cap,10.00uF,+/-10%,25V,X5R,C1206; C_Voltage: 6.3V; Created by: JJJ; Dielectric: X5R; Manufacturer: TDK; Manufacturer PN: C3216X5R1E106K085AC; Priority: A; RK PN: C3216X5R1E106K085AC; Tolerance: 10%; Voltage: 25V
D15-D18 = DIODE_BI_DIR_TRIG_2: 1-Line, Bi-directional, Transient Voltage Suppressors.1pF.; Created by: JJJ; Manufacturer: WillSemi(韦尔半导体); Manufacturer PN: ESD5341N; Part Type: ESD_TVS; Priority: A; RK PN: ESD5341N
D19 = LED: LED绿色发光二极管/SMD/0805无铅; REUSE_ANNOTATE: TRUE
FB18-FB26 = FB: Part Type: R0402
J13-J16 = CON7
Q6 Q12 = MMBT3904_SOT: REUSE_ANNOTATE: TRUE
R88-R99 R101 R103 R105-R111 = RESISTOR_2: 通用厚膜电阻,22R,+/-5%,R0402,1/16W.; Created by: YTL; Manufacturer: YAGEO; Manufacturer PN: RC0402JR-0722RL; Part Type: 通用厚膜电阻; Priority: A; RK PN: RC0402JR-0722RL; Tolerance: 5%; Wattage: 1/16W
R100 R102 R104 R129 R134-R136 = RESISTOR: Part Name: 普通贴片电阻
U13 = RAPTOR3_3
Y2 = OSC
C235-C242 = CAP_NP: cap,220.00nF,+/-10%,10V,X5R,C0201; Created by: JJJ; Dielectric: X5R; Manufacturer: TDK; Manufacturer PN: C0603X5R1A224K030BB; Priority: A; RK PN: C0603X5R1A224K030BB; Tolerance: 10%; Voltage: 10V
C243 = CAP_NP: cap,100.00pF,+/-10%,50V,C0G,C0402; C_Voltage: 10V; Created by: JJJ; Dielectric: C0G; Manufacturer: TDK; Manufacturer PN: C1005C0G1H101K050BA; Number: 37; Priority: A; RK PN: C1005C0G1H101K050BA; Tolerance: 10%; Voltage: 50V
C244 = CAP_NP: cap,1.00uF,+/-10%,10V,X5R,C0402; C_Voltage: 10V; Created by: JJJ; Dielectric: X5R; Manufacturer: TDK; Manufacturer PN: C1005X5R1A105K050BB; Number: 37; Priority: A; RK PN: C1005X5R1A105K050BB; Tolerance: 10%; Voltage: 10V
C245 C246 = CAP_NP: cap,1.00uF,+/-20%,6.3V,X5R,C0201; Created by: JJJ; Dielectric: X5R; Manufacturer: TDK; Manufacturer PN: C0603X5R0J105M030BC; Priority: A; RK PN: C0603X5R0J105M030BC; Tolerance: 20%; Voltage: 6.3V
D20 = DIODE: Schottky Barrier，B5819WS SOD-323; Created by: JJJ; Manufacturer: 长电; Part Type: Schottky rectifier; Priority: A
D21 = DIODE: Schottky Barrier，B5819WS SOD-323; Created by: JJJ; Manufacturer: 长电; Part Type: Schottky rectifier; Priority: A; option: DNP
D22 = DIODE: Schottky Barrier，B5819W SOD-123; Created by: JJJ; Manufacturer: 长电; Part Type: Schottky rectifier; Priority: A
ED2 ED3 = ESD_ESD5304D: 4-Lines, Uni-directional, Ultra-low Capacitance Transient Voltage Suppressors; Created by: JJJ; Manufacturer: WillSemi(韦尔半导体); Manufacturer PN: ESD5304D; Part Type: ESD_TVS; Priority: A; RK PN: ESD5304D
D27-D32 ED4-ED8 = DIODE_BI_DIR_TRIG: 1-Line, Bi-directional, Transient Voltage Suppressors.1pF.; Created by: JJJ; Manufacturer: WillSemi(韦尔半导体); Part Type: ESD_TVS; Priority: A
J17 = HDMI_TYPE_A_0
Q7-Q11 = MOSFET_N: NMOS,2SK3018,SOT_323,Id=0.1A,Vds=30V; Created by: JJJ; Id_max: 0.1A; Manufacturer: ROHM; Part Type: NMOS; Pd: 0.2W; Priority: A; Rds: 5ohm; VDS: 30V; Vgs: 20V; Vgsth: 1.5V
R112 R114 = RESISTOR: 通用厚膜电阻,10K,+/-5%,R0402,1/16W.; Created by: YTL; Manufacturer: YAGEO; Manufacturer PN: RC0402JR-0710KL; Part Type: 通用厚膜电阻; Priority: A; RK PN: RC0402JR-0710KL; Tolerance: 5%; Wattage: 1/16W
R113 R116 R176 R220 = RESISTOR: 通用厚膜电阻,1K8,+/-5%,R0402,1/16W.; Created by: YTL; Manufacturer: YAGEO; Manufacturer PN: RC0402JR-071K8L; Part Type: 通用厚膜电阻; Priority: A; RK PN: RC0402JR-071K8L; Tolerance: 5%; Wattage: 1/16W
R115 = RESISTOR: 通用厚膜电阻,1K,+/-5%,R0402,1/16W.; Created by: YTL; Manufacturer: YAGEO; Manufacturer PN: RC0402JR-071KL; Part Type: 通用厚膜电阻; Priority: A; RK PN: RC0402JR-071KL; Tolerance: 5%; Wattage: 1/16W
R117 = RESISTOR: 通用厚膜电阻,27K,+/-5%,R0402,1/16W.; Created by: YTL; Manufacturer: YAGEO; Manufacturer PN: RC0402JR-0727KL; Part Type: 通用厚膜电阻; Priority: A; RK PN: RC0402JR-0727KL; Tolerance: 5%; Wattage: 1/16W
R118 = RESISTOR: 通用厚膜电阻,27K,+/-5%,R0402,1/16W.; Created by: YTL; Manufacturer: YAGEO; Manufacturer PN: RC0402JR-0727KL; OPTION: DNP; Part Type: 通用厚膜电阻; Priority: A; RK PN: RC0402JR-0727KL; Tolerance: 5%; Wattage: 1/16W
R119 R120 R122 = RESISTOR: 通用厚膜电阻,47K,+/-5%,R0402,1/16W.; Created by: YTL; Manufacturer: YAGEO; Manufacturer PN: RC0402JR-0747KL; Part Type: 通用厚膜电阻; Priority: A; RK PN: RC0402JR-0747KL; Tolerance: 5%; Wattage: 1/16W
R121 = RESISTOR: 通用厚膜电阻,1K2,+/-5%,R0402,1/16W.; Created by: YTL; Manufacturer: YAGEO; Manufacturer PN: RC0402JR-071K2L; Part Type: 通用厚膜电阻; Priority: A; RK PN: RC0402JR-071K2L; Tolerance: 5%; Wattage: 1/16W
C247 = CAP_NP_6: cap,4.70uF,+/-10%,10V,X5R,C0603; C_Voltage: 6.3V; Created by: JJJ; Dielectric: X5R; Manufacturer: TDK; Manufacturer PN: C1608X5R1A475K080AC; Priority: A; RK PN: C1608X5R1A475K080AC; Tolerance: 10%; Voltage: 10V
C248 C257 = CAP_NP_6: cap,100.00nF,+/-10%,10V,X5R,C0402; C_Voltage: 6.3V; Created by: JJJ; Dielectric: X5R; Manufacturer: TDK; Manufacturer PN: C1005X5R1A104K050BA; Number: 37; Priority: A; RK PN: C1005X5R1A104K050BA; Tolerance: 10%; Voltage: 50V
C251-C255 = CAP_NP_6: cap,4.70uF,+/-10%,10V,X5R,C0603; C_Voltage: 6.3V; Created by: JJJ; Dielectric: X5R; Manufacturer: TDK; Manufacturer PN: C1608X5R1A475K080AC; Part Type: C0603; Priority: A; RK PN: C1608X5R1A475K080AC; Tolerance: 10%; Voltage: 10V
C256 = CAP_NP_6: cap,4.70uF,+/-10%,10V,X5R,C0603; C_Voltage: 6.3V; Created by: JJJ; Dielectric: X5R; Manufacturer: TDK; Manufacturer PN: C1608X5R1A475K080AC; Part Type: C0603; Priority: A; RK PN: C1608X5R1A475K080AC; Tolerance: 10%; Voltage: 50V
D23 = DIODE_BI_DIR_TRIG_1: 1-Line, Bi-directional, Transient Voltage Suppressors.1pF.; Created by: JJJ; Manufacturer: WillSemi(韦尔半导体); Manufacturer PN: ESD5341N; Part Type: ESD_TVS; Priority: A; RK PN: ESD5341N
D43 = LED_4: REUSE_ANNOTATE: TRUE
F2 = FB
J18 = CON8_1
L5 = INDUCTOR: Did Not Place.; Created by: JJJ; Part Type: IND; Priority: A; RK PN: DNPL0402
R123-R128 = RESISTOR_2: 通用厚膜电阻,0R,+/-5%,R0402,1/16W.; Created by: YTL; Manufacturer: YAGEO; Manufacturer PN: RC0402JR-070RL; Part Type: 通用厚膜电阻; Priority: A; RK PN: RC0402JR-070RL; Tolerance: 5%; Wattage: 1/16W
R130-R133 = RESISTOR_9: 通用厚膜电阻,0R,+/-5%,R0402,1/16W.; Created by: YTL; Manufacturer: YAGEO; Manufacturer PN: RC0402JR-070RL; Part Type: 通用厚膜电阻; Priority: A; RK PN: RC0402JR-070RL; Tolerance: 5%; Wattage: 1/16W
R348 = R_6: %182%%238%%182%%168%%185%%166%%194%%202%(W): 0.06; %195%%232%%202%%246%: 片式厚膜电阻器-0.0625W-100000ohm-+/-1%-0402; %208%%161%%192%%224%%195%%251%%179%%198%: 片式厚膜电阻器; %215%%232%%214%%181%%212%%202%%208%%237%%198%%171%%178%%238%: +/-1%; CODE: 7090875; COMPONENT_HIGH_MAX: 0.4mm; PKG_TYPE: SR0402; REUSE_ANNOTATE: TRUE; VARIANT_ID: $15I1764
U14 = BL-M8852BS2
U15 = HX6512_0
C258 C259 C283 C284 = CAP_NP: cap,18.00pF,+/-5%,50V,C0G,C0402; Created by: JJJ; Dielectric: C0G; Manufacturer: TDK; Manufacturer PN: C1005C0G1H180J050BA; Priority: A; RK PN: C1005C0G1H180J050BA; Tolerance: 5%; Voltage: 50V
C260-C263 C285-C288 = CAP_NP: cap,10.00nF,+/-10%,25V,X5R,C0402; Created by: JJJ; Dielectric: X5R; Manufacturer: TDK; Manufacturer PN: C1005X5R1E103K050BA; Priority: A; RK PN: C1005X5R1E103K050BA; Tolerance: 10%; Voltage: 25V
C264 C282 C289 C304 = CAP_NP: Did Not Place.; C_Voltage: 6.3V; Created by: JJJ; Manufacturer PN: DNPC0402; Number: 37; Priority: A; RK PN: DNPC0402
C265 C290 = CAP_NP: 高压电容,1000pF/2KV,C1206; Created by: JJJ; Manufacturer PN: CTY1AC250V2E4102M2B; Part Type: 高压电容; Priority: A; RK PN: CTY1AC250V2E4102M2B; Tolerance: 20%; Voltage: 2KV
C266 C269 C272 C275 = CAP_NP: cap,4.70uF,+/-10%,10V,X5R,C0603; C_Voltage: 6.3V; Created by: JJJ; Dielectric: X5R; Manufacturer: TDK; Manufacturer PN: C1608X5R1A475K080AC; Priority: A; RK PN: C1608X5R1A475K080AC; Tolerance: 10%; Voltage: 10V
C267 = CAP_NP: cap,1.00uF,+/-10%,6.3V,X5R,C0402; C_Voltage: 6.3V; Created by: JJJ; Dielectric: X5R; Manufacturer: TDK; Manufacturer PN: C1005X5R0J105K050BB; Priority: A; RK PN: C1005X5R0J105K050BB; Tolerance: 10%; Voltage: 6.3V
C268 C270 C271 C273 C276 C277 C279-C281 C324 = CAP_NP: cap,100.00nF,+/-10%,10V,X5R,C0402; C_Voltage: 6.3V; Created by: JJJ; Dielectric: X5R; Manufacturer: TDK; Manufacturer PN: C1005X5R1A104K050BA; Number: 37; Priority: A; RK PN: C1005X5R1A104K050BA; Tolerance: 10%; Voltage: 10V
C274 = CAP_NP: cap,3.00pF,+/-0.25,50V,C0G,C0402; Created by: JJJ; Dielectric: C0G; Manufacturer: TDK; Manufacturer PN: C1005C0G1H030C050BA; Priority: A; RK PN: C1005C0G1H030C050BA; Tolerance: +/-0.25pF; Voltage: 50V; option: DNP
C278 = CAP_NP: cap,100.00nF,+/-10%,10V,X5R,C0402; Created by: JJJ; Dielectric: X5R; Manufacturer: TDK; Manufacturer PN: C1005X5R1A104K050BA; Priority: A; RK PN: C1005X5R1A104K050BA; Tolerance: 10%; Voltage: 10V
J27 J28 = CON8A
L6 L7 = INDUCTORS_OF_FERRITE: Power Inductor,2.2uH,0.3,IND_303015; Created by: YTL; DC Resistor: 0.06ohm; Irms: 1.6A; Isat: 1.6A; Manufacturer: sunlord; Manufacturer PN: SWPA3015S2R2NT; Part Type: POWER_IND; Priority: A; RK PN: SWPA3015S2R2NT; Resonace frequency: 86M; Tolerance: 30%
R137 R138 R141-R143 R145-R147 R167 R172 R177 R184 R185 R187-R192 R211 R216 R221 = RESISTOR: 通用厚膜电阻,0R,+/-5%,R0402,1/16W.; Created by: YTL; Manufacturer: YAGEO; Manufacturer PN: RC0402JR-070RL; Part Type: 通用厚膜电阻; Priority: A; RK PN: RC0402JR-070RL; Tolerance: 5%; Wattage: 1/16W
R140 = RESISTOR: 通用厚膜电阻,0R,+/-5%,R0402,1/16W.; Created by: YTL; Manufacturer: YAGEO; Manufacturer PN: RC0402JR-070RL; Part Type: 通用厚膜电阻; Priority: A; RK PN: RC0402JR-070RL; Tolerance: 5%; Wattage: 1/16W; option: DNP
R148 = RESISTOR: 通用厚膜电阻,0R,+/-5%,R0402,1/16W.; Created by: YTL; Manufacturer: YAGEO; Manufacturer PN: RC0402JR-070RL; Option: DNP; Part Type: 通用厚膜电阻; Priority: A; RK PN: RC0402JR-070RL; Tolerance: 5%; Wattage: 1/16W
R150-R153 R194-R197 = RESISTOR: 通用厚膜电阻,75R,+/-5%,R0805,1/8W.; Created by: YTL; Manufacturer: YAGEO; Manufacturer PN: RC0805JR-0775RL; Part Type: 通用厚膜电阻; Priority: A; RK PN: RC0805JR-0775RL; Tolerance: 5%; Wattage: 1/8W
R155 = RESISTOR: 通用厚膜电阻,100R,+/-5%,R0402,1/16W.; Created by: YTL; Manufacturer: YAGEO; Manufacturer PN: RC0402JR-07100RL; Option: DNP; Part Type: 通用厚膜电阻; Priority: A; RK PN: RC0402JR-07100RL; Tolerance: 5%; Wattage: 1/16W
R156 = RESISTOR: 通用厚膜电阻,120R,+/-5%,R0402,1/16W.; Created by: YTL; Manufacturer: YAGEO; Manufacturer PN: RC0402JR-07120RL; Option: DNP; Part Type: 通用厚膜电阻; Priority: A; RK PN: RC0402JR-07120RL; Tolerance: 5%; Wattage: 1/16W
R157 R160 R161 R163 R165 R166 R169 R170 R174 R201 R202 R204 R206 R208-R210 R213 R214 R218 = RESISTOR: 通用厚膜电阻,4K7,+/-5%,R0402,1/16W.; Created by: YTL; Manufacturer: YAGEO; Manufacturer PN: RC0402JR-074K7L; Part Type: 通用厚膜电阻; Priority: A; RK PN: RC0402JR-074K7L; Tolerance: 5%; Wattage: 1/16W
R158 R159 R164 R168 R171 R173 R200 R207 R215 R217 = RESISTOR: 通用厚膜电阻,4K7,+/-5%,R0402,1/16W.; Created by: YTL; Manufacturer: YAGEO; Manufacturer PN: RC0402JR-074K7L; Part Type: 通用厚膜电阻; Priority: A; RK PN: RC0402JR-074K7L; Tolerance: 5%; Wattage: 1/16W; option: DNP
R162 R205 = RESISTOR: 通用厚膜电阻,2K49,+/-1%,R0402,1/16W.; Created by: YTL; Manufacturer: YAGEO; Manufacturer PN: RC0402FR-072K49L; Part Type: 通用厚膜电阻; Priority: A; RK PN: RC0402FR-072K49L; Tolerance: 1%; Wattage: 1/16W
R175 R219 = RESISTOR: 通用厚膜电阻,4K7,+/-5%,R0402,1/16W.; Created by: YTL; Manufacturer: YAGEO; Manufacturer PN: RC0402JR-074K7L; Option: DNP; Part Type: 通用厚膜电阻; Priority: A; RK PN: RC0402JR-074K7L; Tolerance: 5%; Wattage: 1/16W
R178-R183 R222-R227 R252-R256 R359 = RESISTOR: 通用厚膜电阻,22R,+/-5%,R0402,1/16W.; Created by: YTL; Manufacturer: YAGEO; Manufacturer PN: RC0402JR-0722RL; Part Type: 通用厚膜电阻; Priority: A; RK PN: RC0402JR-0722RL; Tolerance: 5%; Wattage: 1/16W
TP7 = TP: Test Point 0.7mm; Created by: JJJ; Priority: A; RK PN: TESTPOINT_0R7
U16 U18 = Ethernet_H5007: Gigabit Ethernet (1000Base-T); Created by: JJJ; Manufacturer: Pulse; Part Type: Ethernet; Priority: A
U17 U19 = Ethernet_RTL8211F: Integrated 10/100/1000 Gigabit Ethernet Transceiver，Supports IEEE 802.3az-2010,; Created by: JJJ; Manufacturer: RealTek(瑞昱); Part Type: Ethernet; Priority: A
Y3 Y4 = CRYSTAL_4P: 无源晶振，25M，3225,±10ppm，10pF，Hosonic; Created by: JJJ; Manufacturer: Hosonic(鸿星电子); Manufacturer PN: E3SB25.0000F10E11; Part Type: CRYSTAL; Priority: A; RK PN: E3SB25.0000F10E11
C291 C294 C298 C301 = CAP_NP: cap,4.70uF,+/-10%,10V,X5R,C0402; C_Voltage: 6.3V; Created by: JJJ; Dielectric: X5R; Manufacturer: TDK; Manufacturer PN: C1005X5R1A475K050BC; Priority: A; RK PN: C1005X5R1A475K050BC; Tolerance: 10%; Voltage: 10V
C292 = CAP_NP: cap,1.00uF,+/-10%,16V,X5R,C0402; C_Voltage: 6.3V; Created by: JJJ; Dielectric: X5R; Manufacturer: TDK; Manufacturer PN: C1005X5R1C105K050BC; Priority: A; RK PN: C1005X5R1C105K050BC; Tolerance: 10%; Voltage: 16V
C293 C295 C296 C299 C302 C303 C305-C307 = CAP_NP: cap,100.00nF,+/-10%,16V,X5R,C0402; C_Voltage: 6.3V; Created by: JJJ; Dielectric: X5R; Manufacturer: TDK; Manufacturer PN: C1005X5R1C104K050BA; Number: 37; Priority: A; RK PN: C1005X5R1C104K050BA; Tolerance: 10%; Voltage: 16V
C297 = CAP_NP: cap,3.00pF,+/-0.25,50V,C0G,C0201; Created by: JJJ; Dielectric: C0G; Manufacturer: TDK; Manufacturer PN: C0603C0G1H030C030BA; OPTION: DNP; Priority: A; RK PN: C0603C0G1H030C030BA; Tolerance: +/-0.25pF; Voltage: 50V
C300 = CAP_NP: cap,100.00nF,+/-10%,16V,X5R,C0402; Created by: JJJ; Dielectric: X5R; Manufacturer: TDK; Manufacturer PN: C1005X5R1C104K050BA; Priority: A; RK PN: C1005X5R1C104K050BA; Tolerance: 10%; Voltage: 16V
R186 R193 = RESISTOR: 通用厚膜电阻,0R,+/-5%,R0402,1/16W.; Created by: YTL; Manufacturer: YAGEO; Manufacturer PN: RC0402JR-070RL; OPTION: DNP; Part Type: 通用厚膜电阻; Priority: A; RK PN: RC0402JR-070RL; Tolerance: 5%; Wattage: 1/16W
R198 = RESISTOR: 通用厚膜电阻,100R,+/-5%,R0402,1/16W.; Created by: YTL; Manufacturer: YAGEO; Manufacturer PN: RC0402JR-07100RL; OPTION: DNP; Part Type: 通用厚膜电阻; Priority: A; RK PN: RC0402JR-07100RL; Tolerance: 5%; Wattage: 1/16W
R199 = RESISTOR: 通用厚膜电阻,120R,+/-5%,R0402,1/16W.; Created by: YTL; Manufacturer: YAGEO; Manufacturer PN: RC0402JR-07120RL; OPTION: DNP; Part Type: 通用厚膜电阻; Priority: A; RK PN: RC0402JR-07120RL; Tolerance: 5%; Wattage: 1/16W
R203 R212 = RESISTOR: 通用厚膜电阻,4K7,+/-5%,R0402,1/16W.; Created by: YTL; Manufacturer: YAGEO; Manufacturer PN: RC0402JR-074K7L; OPTION: DNP; Part Type: 通用厚膜电阻; Priority: A; RK PN: RC0402JR-074K7L; Tolerance: 5%; Wattage: 1/16W
C321 C322 C378 C379 = CAP_v2: Capacitor-4.7uF,+/-20%,X5R,6.3V-0402; Part Number: 02.0018.00; Part Type: 0402表贴普通电容; 供应商: 国巨 / Murata; 规格型号1: CC0402MRX5R5BB475 / GRM153R60J475ME15D; 联系人: 谢苏云; 手机: 15900554174; 邮箱: susan.xie@murata.com
C323 = CAP_NP: cap,10.00uF,+/-10%,10V,X5R,C0603; C_Voltage: 6.3V; Created by: JJJ; Dielectric: X5R; Manufacturer: TDK; Manufacturer PN: C1608X5R1A106K080AC; Priority: A; RK PN: C1608X5R1A106K080AC; Tolerance: 10%; Voltage: 10V
D26 = DIODE_BI_DIR_TRIG: 1-Line, Bi-directional, Transient Voltage Suppressors.9pF.; Created by: JJJ; Manufacturer: WillSemi(韦尔半导体); Part Type: ESD_TVS; Priority: A
J22 = TFCARD_SOCKET: 通用TF卡座，全尺寸; Created by: JJJ; Manufacturer: 旺科达; Part Type: CARD Jack; Priority: A
R248 R250 R360 = RESISTOR_1: 通用厚膜电阻,1K,+/-5%,R0402,1/16W.; Created by: YTL; Manufacturer: YAGEO; Manufacturer PN: RC0402JR-071KL; Part Type: 通用厚膜电阻; Priority: A; RK PN: RC0402JR-071KL; Tolerance: 5%; Wattage: 1/16W
U22 = GL835_P2P_RTS5141_0

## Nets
1V2_PLL1: C212.1 C213.1 FB22.2 U13.113(VDD1A_PLL)
1V2A_V5: C210.1 C211.1 FB21.2 U13.8(VDD1A1) U13.14(VDD1A2)
1V2A_V6: C221.1 C222.1 FB24.2 U13.20(VDD1A3) U13.26(VDD1A4)
1V2A_V7: C223.1 C224.1 FB25.2 U13.38(VDD1A5) U13.66(VDD1A6)
1V2A_V8: C225.1 C226.1 FB26.2 U13.92(VDD1A7)
1V2D1: C214.1 C215.1 C216.1 C217.1 C218.1 C219.1 C220.1 FB23.2 U13.5(VDD1D1) U13.43(VDD1D2) U13.48(VDD1D3) U13.53(VDD1D4) U13.59(VDD1D5) U13.65(VDD1D6) U13.78(VDD1D7) U13.80(VDD1D8) U13.93(VDD1D9) U13.102(VDD1D10) U13.112(VDD1D11) U13.114(VDD1D12) U13.124(VDD1D13)
3V3A_AHD2: C198.1 C199.1 C200.1 C201.1 C202.1 FB19.2 U13.11(VDD3A1) U13.17(VDD3A2) U13.23(VDD3A3) U13.29(VDD3A4) U13.37(VDD3A5) U13.39(VDD3A6) U13.67(VDD3A7) U13.91(VDD3A8)
3V3D_AHD2: C203.1 C204.1 C205.1 C206.1 C207.1 C208.1 C209.1 FB20.2 R106.2 R107.1 R109.1 R110.1 U13.2(VDD3D1) U13.42(VDD3D2) U13.51(VDD3D3) U13.58(VDD3D4) U13.64(VDD3D5) U13.79(VDD3D6) U13.96(VDD3D7) U13.100(VDD3D8) U13.107(VDD3D9) U13.115(VDD3D10) U13.123(VDD3D11) U13.128(VDD3D12)
DGND: C182.1 C184.1 C188.1 C189.1 C190.1 C191.2 C192.1 C193.1 C195.1 C196.2 C197.2 C198.2 C199.2 C200.2 C201.2 C202.2 C203.2 C204.2 C205.2 C206.2 C207.2 C208.2 C209.2 C210.2 C211.2 C212.2 C213.2 C214.2 C215.2 C216.2 C217.2 C218.2 C219.2 C220.2 C221.2 C222.2 C223.2 C224.2 C225.2 C226.2 C227.2 C228.2 C229.2 C230.2 C231.2 C232.2 C233.2 C234.2 C244.2 C247.2 C248.2 C249.2 C250.2 C251.2 C252.2 C253.2 C254.2 C255.2 C256.1 C257.1 C258.2 C259.2 C260.2 C261.2 C262.2 C263.2 C264.2 C265.2 C266.2 C267.2 C268.2 C269.2 C270.2 C271.2 C272.2 C273.2 C274.2 C275.2 C276.2 C277.2 C278.2 C279.2 C280.2 C281.2 C282.2 C283.2 C284.2 C285.2 C286.2 C287.2 C288.2 C289.2 C290.2 C291.2 C292.2 C293.2 C294.2 C295.2 C296.2 C297.2 C298.2 C299.2 C300.2 C301.2 C302.2 C303.2 C304.2 C305.2 C306.2 C307.2 C321.2 C322.2 C323.2 C324.2 C378.2 C379.1 D15.2 D16.2 D17.2 D18.2 D23.2 D26.2 D27.2 D28.2 D29.2 D30.2 D31.2 D32.2 ED2.3(GND) ED2.8(GND) ED3.3(GND) ED3.8(GND) ED4.2 ED5.2 ED6.2 ED7.2 ED8.2 J13.2 J13.3 J13.4 J13.6 J13.7 J14.2 J14.3 J14.4 J14.6 J14.7 J15.2 J15.3 J15.4 J15.6 J15.7 J16.2 J16.3 J16.4 J16.6 J16.7 J17.2(D2_G) J17.5(D1_G) J17.8(D0_G) J17.11(CLK_G) J17.17(GND) J17.20(G1) J17.21(G2) J17.22(G3) J17.23(G4) J18.5 J18.6 J18.7 J18.8 J22.6(VSS) J22.10(G1) J22.11(G2) J22.12(G3) J22.13(G4) Q6.2(E) Q10.2(SOURCE) Q11.2(SOURCE) Q12.2(E) R90.2 R93.2 R94.1 R95.1 R96.1 R97.2 R98.1 R99.2 R104.2 R108.1 R111.1 R122.1 R136.2 R140.2 R156.2 R157.2 R159.2 R161.2 R162.2 R163.2 R165.2 R166.2 R168.2 R170.2 R173.2 R186.2 R199.2 R200.2 R202.2 R204.2 R205.2 R207.2 R209.2 R210.2 R212.2 R214.2 R217.2 R248.1 R250.1 R360.1 U13.1(VSS1) U13.44(TEST) U13.101(VSS2) U13.103(VSS3) U13.104(VSS4) U13.105(VSS5) U13.106(VSS6) U13.108(VSS7) U13.109(VSS8) U13.110(VSS9) U13.111(VSS10) U13.118(VSS11) U13.119(VSS12) U13.120(VSS13) U13.121(VSS14) U13.122(VSS15) U13.125(VSS16) U13.126(VSS17) U13.127(VSS18) U13.129(PGND) U14.1(GND1) U14.3(GND3) U14.4(GND4) U14.5(GND5) U14.6(GND6) U14.7(GND7) U14.8(GND8) U14.10(GND10) U14.11(GND11) U14.13(GND12) U14.23(GND13) U14.32(GND14) U14.39(GND15) U14.46(GND16) U14.48(GND17) U15.10(GND1) U15.12(GND2) U15.13(GND3) U15.24(GND4) U17.41(E_Pad) U19.41(E_Pad) U22.25(GND) Y2.2(GND) Y3.2(GND) Y3.4(GND) Y4.2(GND) Y4.4(GND) ; also on sheet 1 2 3 4 5 6 13 14 15 16 17
VCC1V2: FB21.1 FB22.1 FB23.1 FB24.1 FB25.1 FB26.1 ; also on sheet 6
VCC3V3_PHY0: C269.1 C270.1 C271.1 C272.1 C273.1 R158.1 R160.1 R172.2 R175.1 U17.11(AVDD33) U17.29(DVDD33) U17.40(AVDD33)
VCC3V3_PHY1: C294.1 C295.1 C296.1 C298.1 C299.1 R201.1 R203.1 R206.2 R216.2 R219.1 U19.11(AVDD33) U19.29(DVDD33) U19.40(AVDD33)
VCC3V3_SD: C323.1 C324.1 J22.4(VDD) U22.7(SD_VCC)
VCC3V3_SYS: C257.2 C321.1 C322.1 D19.1(a) D21.1(A) D43.3 F2.1 FB18.1 FB19.1 FB20.1 Q7.1(GATE) R112.1 R114.1 R115.1 R117.1 R130.1 R172.1 R211.1 R216.1 U22.5(A3V3) U22.6(D3V3) ; also on sheet 1 3 4 5 6 14 15 16 17
VCC3V9_5G: D43.1 ; also on sheet 2 3 5
VCC5V0_SYS: D20.1(A) D22.1(A) Q9.1(GATE) ; also on sheet 1 3 4 16
VCC5V_HDMI_TX0: C244.1 D22.2(K) J17.18(+5V)
VCC_1V8: R119.2 R120.2 R133.1 R167.1 ; also on sheet 3 4 13 15
VCC_DCIN: C227.1 C228.1 C229.1 C230.1 C231.1 C232.1 C233.1 C234.1 J13.1 J14.1 J15.1 J16.1 ; also on sheet 3 6
VCCIO_PHY0: C266.1 C267.1 C268.1 R164.1 R167.2 R169.1 R171.1 R174.1 R176.1 U17.28(DVDD_RG)
VCCIO_PHY1: C291.1 C292.1 C293.1 R208.1 R211.2 R213.1 R215.1 R218.1 R220.1 U19.28(DVDD_RG)
VCCIO_WL: C255.1 R129.1 R133.2 U14.34(VDDIO)
VDD10_PHY0: C275.1 C276.1 C277.1 C279.1 C280.1 C281.1 L6.2 U17.3(AVDD10) U17.8(AVDD10) U17.21(DVDD10) U17.38(AVDD10)
VDD10_PHY1: C301.1 C302.1 C303.1 C305.1 C306.1 C307.1 L7.2 U19.3(AVDD10) U19.8(AVDD10) U19.21(DVDD10) U19.38(AVDD10)
VINN5: C176.1 R90.1
VINN6: C178.1 R93.1
VINN7: C179.1 R99.1
VINN8: C187.1 R97.1
VINP5: C175.1 R88.2 R94.2
VINP5_COAX: D15.1 J13.5 R88.1
VINP6: C177.1 R91.2 R95.2
VINP6_COAX: D16.1 J14.5 R91.1
VINP7: C186.1 R89.2 R98.2
VINP7_COAX: D17.1 J15.5 R89.1
VINP8: C180.1 R92.2 R96.2
VINP8_COAX: D18.1 J16.5 R92.1
5G_WWAN_LED#: R348.1 ; also on sheet 5
27M_CLK_XI1: C197.1 R101.2 R105.1 Y2.3(OUT)
AHD_I2C_SCL: R107.2 U13.49(SCL) ; also on sheet 2 6
AHD_I2C_SDA: R106.1 U13.50(SDA) ; also on sheet 2 6
AHD_RSTN: U13.47(RSTB) ; also on sheet 2 6
BT&WIFI_ANT: C254.1 J18.2 R132.1
BT_RST: U14.38(BT-DIS) ; also on sheet 2
BT_WAKE_HOST_H: U14.50(BT_WAKE_HOST) ; also on sheet 2
ETH0_REFCLKO_25M: R148.1 ; also on sheet 2
ETH1_REFCLKO_25M: R193.1 ; also on sheet 2
GMAC0_MCLKINOUT: C264.1 R155.1 R156.1 ; also on sheet 2
GMAC0_MDC: U17.13(MDC) ; also on sheet 2
GMAC0_MDIO: R176.2 U17.14(MDIO) ; also on sheet 2
GMAC0_RSTn_L: R177.1 ; also on sheet 2
GMAC0_RXCLK: C282.1 R182.2 ; also on sheet 2
GMAC0_RXD0: R178.2 ; also on sheet 2
GMAC0_RXD1: R179.2 ; also on sheet 2
GMAC0_RXD2: R180.2 ; also on sheet 2
GMAC0_RXD3: R181.2 ; also on sheet 2
GMAC0_RXDV_CRS: R183.2 ; also on sheet 2
GMAC0_TXCLK: C274.1 U17.20(TXC) ; also on sheet 2
GMAC0_TXD0: U17.18(TXD0) ; also on sheet 2
GMAC0_TXD1: U17.17(TXD1) ; also on sheet 2
GMAC0_TXD2: U17.16(TXD2) ; also on sheet 2
GMAC0_TXD3: U17.15(TXD3) ; also on sheet 2
GMAC0_TXEN: U17.19(TXCTL) ; also on sheet 2
GMAC1_MCLKINOUT: C289.1 R198.1 R199.1 ; also on sheet 2
GMAC1_MDC: U19.13(MDC) ; also on sheet 2
GMAC1_MDIO: R220.2 U19.14(MDIO) ; also on sheet 2
GMAC1_RSTn_L: R221.1 ; also on sheet 2
GMAC1_RXCLK: C304.1 R226.2 ; also on sheet 2
GMAC1_RXD0: R222.2 ; also on sheet 2
GMAC1_RXD1: R223.2 ; also on sheet 2
GMAC1_RXD2: R224.2 ; also on sheet 2
GMAC1_RXD3: R225.2 ; also on sheet 2
GMAC1_RXDV_CRS: R227.2 ; also on sheet 2
GMAC1_TXCLK: C297.1 U19.20(TXC) ; also on sheet 2
GMAC1_TXD0: U19.18(TXD0) ; also on sheet 2
GMAC1_TXD1: U19.17(TXD1) ; also on sheet 2
GMAC1_TXD2: U19.16(TXD2) ; also on sheet 2
GMAC1_TXD3: U19.15(TXD3) ; also on sheet 2
GMAC1_TXEN: U19.19(TXCTL) ; also on sheet 2
GNSS_ANT: J18.1 L5.1 U15.11(RF_IN)
GNSS_RST: U15.8(CHIP_EN) ; also on sheet 16
GNSS_STATE: R135.1 ; also on sheet 16
HDMI0_eARC+: C245.2 ED8.1 J17.14(Utility)
HDMI0_eARC-: C246.2 ED4.1 J17.19(HPD) R121.2
HDMI0_TX0N_PORT: C240.2 ED3.2(IO2) ED3.9(NC) J17.9(D0N)
HDMI0_TX0N_PORT/eDP0_TX_D0N: C240.1 ; also on sheet 2
HDMI0_TX0P_PORT: C239.2 ED3.1(IO1) ED3.10(NC) J17.7(D0P)
HDMI0_TX0P_PORT/eDP0_TX_D0P: C239.1 ; also on sheet 2
HDMI0_TX1N_PORT: C238.2 ED2.5(IO4) ED2.6(NC) J17.6(D1N)
HDMI0_TX1N_PORT/eDP0_TX_D1N: C238.1 ; also on sheet 2
HDMI0_TX1P_PORT: C237.2 ED2.4(IO3) ED2.7(NC) J17.4(D1P)
HDMI0_TX1P_PORT/eDP0_TX_D1P: C237.1 ; also on sheet 2
HDMI0_TX2N_PORT: C236.2 ED2.2(IO2) ED2.9(NC) J17.3(D2N)
HDMI0_TX2N_PORT/eDP0_TX_D2N: C236.1 ; also on sheet 2
HDMI0_TX2P_PORT: C235.2 ED2.1(IO1) ED2.10(NC) J17.1(D2P)
HDMI0_TX2P_PORT/eDP0_TX_D2P: C235.1 ; also on sheet 2
HDMI0_TX3N_PORT: C242.2 ED3.5(IO4) ED3.6(NC) J17.12(CLKN)
HDMI0_TX3N_PORT/eDP0_TX_D3N: C242.1 ; also on sheet 2
HDMI0_TX3P_PORT: C241.2 ED3.4(IO3) ED3.7(NC) J17.10(CLKP)
HDMI0_TX3P_PORT/eDP0_TX_D3P: C241.1 ; also on sheet 2
HDMI0_TX_CEC_PORT: ED7.1 J17.13(CEC) Q9.3(DRAIN) R118.2
HDMI0_TX_SBDN/eDP0_TX_AUXN: C246.1 ; also on sheet 2
HDMI0_TX_SBDP/eDP0_TX_AUXP: C245.1 ; also on sheet 2
HDMI0_TX_SCL_PORT: ED6.1 J17.15(SCL) Q7.3(DRAIN) R113.2
HDMI0_TX_SDA_PORT: ED5.1 J17.16(SDA) Q8.3(DRAIN) R116.2
HDMITX0_CEC_M0: Q9.2(SOURCE) R117.2 ; also on sheet 2
HDMITX0_HPDIN: Q10.3(DRAIN) R119.1 ; also on sheet 2
HDMITX0_SCL_M0: Q7.2(SOURCE) R112.2 ; also on sheet 2
HDMITX0_SDA_M0: C243.2 Q8.2(SOURCE) R114.2 ; also on sheet 2
HOST_WAKE_BT_H: U14.49(HOST_WAKE_BT) ; also on sheet 2
LAN0_A+: J28.1 U16.23(MX1+)
LAN0_A-: J28.2 U16.22(MX1-)
LAN0_B+: J28.3 U16.20(MX2+)
LAN0_B-: J28.6 U16.19(MX2-)
LAN0_C+: J28.4 U16.17(MX3+)
LAN0_C-: J28.5 U16.16(MX3-)
LAN0_D+: J28.7 U16.14(MX4+)
LAN0_D-: J28.8 U16.13(MX4-)
LAN0_MCT1: R153.1 U16.24(MCT1)
LAN0_MCT2: R152.1 U16.21(MCT2)
LAN0_MCT3: R151.1 U16.18(MCT3)
LAN0_MCT4: R150.1 U16.15(MCT4)
LAN1_A+: J27.1 U18.23(MX1+)
LAN1_A-: J27.2 U18.22(MX1-)
LAN1_B+: J27.3 U18.20(MX2+)
LAN1_B-: J27.6 U18.19(MX2-)
LAN1_C+: J27.4 U18.17(MX3+)
LAN1_C-: J27.5 U18.16(MX3-)
LAN1_D+: J27.7 U18.14(MX4+)
LAN1_D-: J27.8 U18.13(MX4-)
LAN1_MCT1: R197.1 U18.24(MCT1)
LAN1_MCT2: R196.1 U18.21(MCT2)
LAN1_MCT3: R195.1 U18.18(MCT3)
LAN1_MCT4: R194.1 U18.15(MCT4)
MIPI_CSI1_RX_CLK0N: U13.85(TX0_CN) ; also on sheet 2
MIPI_CSI1_RX_CLK0P: U13.86(TX0_CP) ; also on sheet 2
MIPI_CSI1_RX_D0N: U13.81(TX0_DN0) ; also on sheet 2
MIPI_CSI1_RX_D0P: U13.82(TX0_DP0) ; also on sheet 2
MIPI_CSI1_RX_D1N: U13.83(TX0_DN1) ; also on sheet 2
MIPI_CSI1_RX_D1P: U13.84(TX0_DP1) ; also on sheet 2
MIPI_CSI1_RX_D2N: U13.87(TX0_DN2) ; also on sheet 2
MIPI_CSI1_RX_D2P: U13.88(TX0_DP2) ; also on sheet 2
MIPI_CSI1_RX_D3N: U13.89(TX0_DN3) ; also on sheet 2
MIPI_CSI1_RX_D3P: U13.90(TX0_DP3) ; also on sheet 2
PHY0_CLKOUT125: R155.2 U17.35(CLKOUT)
PHY0_LED0/CFG_EXT: R157.1 R158.2 U17.32(LED0/CFG_EXT)
PHY0_LED1/CFG_LDO0: R161.1 U17.33(LED1/CFG_LDO0)
PHY0_LED2/CFG_LDO1: R159.1 R160.2 U17.34(LED2/CFG_LDO1)
PHY0_MDI0+: R137.1 U17.1(MDI[0]+)
PHY0_MDI0-: R138.1 U17.2(MDI[0]-)
PHY0_MDI1+: R141.1 U17.4(MDI[1]+)
PHY0_MDI1-: R142.1 U17.5(MDI[1]-)
PHY0_MDI2+: R143.1 U17.6(MDI[2]+)
PHY0_MDI2-: R145.1 U17.7(MDI[2]-)
PHY0_MDI3+: R146.1 U17.9(MDI[3]+)
PHY0_MDI3-: R147.1 U17.10(MDI[3]-)
PHY0_MDI_0+: R137.2 U16.2(TD1+)
PHY0_MDI_0-: R138.2 U16.3(TD1-)
PHY0_MDI_1+: R141.2 U16.5(TD2+)
PHY0_MDI_1-: R142.2 U16.6(TD2-)
PHY0_MDI_2+: R143.2 U16.8(TD3+)
PHY0_MDI_2-: R145.2 U16.9(TD3-)
PHY0_MDI_3+: R146.2 U16.11(TD4+)
PHY0_MDI_3-: R147.2 U16.12(TD4-)
PHY0_REG_OUT: L6.1 U17.30(REG_OUT)
PHY0_RSTn: C278.1 R175.2 R177.2 U17.12(PHYRSTB)
PHY0_RXCLK/PHYAD1: R165.1 R182.1 U17.27(RXC/PHYAD1)
PHY0_RXD0/RXDLY: R168.1 R169.2 R178.1 U17.25(RXD0/RXDLY)
PHY0_RXD1/TXDLY: R170.1 R171.2 R179.1 U17.24(RXD1/TXDLY)
PHY0_RXD2/PLLOFF: R173.1 R174.2 R180.1 U17.23(RXD2/PLLOFF)
PHY0_RXD3/PHYAD0: R163.1 R164.2 R181.1 U17.22(RXD3/PHYAD0)
PHY0_RXDV/PHYAD2: R166.1 R183.1 U17.26(RXCTL/PHYAD2)
PHY0_XTALIN: C259.1 R140.1 U17.36(XTAL_IN) Y3.3(X2)
PHY0_XTALOUT: C258.1 R148.2 U17.37(XTAL_OUT/EXT_CLK) Y3.1(X1)
PHY1_CLKOUT125: R198.2 U19.35(CLKOUT)
PHY1_LED0/CFG_EXT: R200.1 R201.2 U19.32(LED0/CFG_EXT)
PHY1_LED1/CFG_LDO0: R204.1 U19.33(LED1/CFG_LDO0)
PHY1_LED2/CFG_LDO1: R202.1 R203.2 U19.34(LED2/CFG_LDO1)
PHY1_MDI0+: R185.1 U19.1(MDI[0]+)
PHY1_MDI0-: R184.1 U19.2(MDI[0]-)
PHY1_MDI1+: R187.1 U19.4(MDI[1]+)
PHY1_MDI1-: R188.1 U19.5(MDI[1]-)
PHY1_MDI2+: R189.1 U19.6(MDI[2]+)
PHY1_MDI2-: R190.1 U19.7(MDI[2]-)
PHY1_MDI3+: R191.1 U19.9(MDI[3]+)
PHY1_MDI3-: R192.1 U19.10(MDI[3]-)
PHY1_MDI_0+: R185.2 U18.2(TD1+)
PHY1_MDI_0-: R184.2 U18.3(TD1-)
PHY1_MDI_1+: R187.2 U18.5(TD2+)
PHY1_MDI_1-: R188.2 U18.6(TD2-)
PHY1_MDI_2+: R189.2 U18.8(TD3+)
PHY1_MDI_2-: R190.2 U18.9(TD3-)
PHY1_MDI_3+: R191.2 U18.11(TD4+)
PHY1_MDI_3-: R192.2 U18.12(TD4-)
PHY1_REG_OUT: L7.1 U19.30(REG_OUT)
PHY1_RSTn: C300.1 R219.2 R221.2 U19.12(PHYRSTB)
PHY1_RXCLK/PHYAD1: R209.1 R226.1 U19.27(RXC/PHYAD1)
PHY1_RXD0/RXDLY: R212.1 R213.2 R222.1 U19.25(RXD0/RXDLY)
PHY1_RXD1/TXDLY: R214.1 R215.2 R223.1 U19.24(RXD1/TXDLY)
PHY1_RXD2/PLLOFF: R217.1 R218.2 R224.1 U19.23(RXD2/PLLOFF)
PHY1_RXD3/PHYAD0: R207.1 R208.2 R225.1 U19.22(RXD3/PHYAD0)
PHY1_RXDV/PHYAD2: R210.1 R227.1 U19.26(RXCTL/PHYAD2)
PHY1_XTALIN: C284.1 R186.1 U19.36(XTAL_IN) Y4.3(X2)
PHY1_XTALOUT: C283.1 R193.2 U19.37(XTAL_OUT/EXT_CLK) Y4.1(X1)
RSET0: R162.1 U17.39(RSET)
RSET1: R205.1 U19.39(RSET)
SD_CLK: R128.1 ; also on sheet 2
SDMMC0_CMD: R127.1 ; also on sheet 2
SDMMC0_D0: R123.1 ; also on sheet 2
SDMMC0_D1: R124.1 ; also on sheet 2
SDMMC0_D2: R125.1 ; also on sheet 2
SDMMC0_D3: R126.1 ; also on sheet 2
SDMMC_CLK: R359.1 U22.18(SD_CLK)
SDMMC_CMD: R254.1 U22.20(SD_CMD)
SDMMC_D0: R255.1 U22.13(SD_D0)
SDMMC_D1: R256.1 U22.12(SD_D1)
SDMMC_D2: R252.1 U22.23(SD_D2)
SDMMC_D3: R253.1 U22.22(SD_D3)
SDMMC_DET_L: D26.1 J22.9(CD) U22.10(SD_CDZ)
UART3_RX_M0: U15.20(UART0_TX) ; also on sheet 16
UART3_TX_M0: U15.21(UART0_RX) ; also on sheet 16
UART6_CTSN_M1: U14.42(UART_RTS) ; also on sheet 2
UART6_RTSN_M1: U14.43(UART_CTS) ; also on sheet 2
UART6_RX_M1: U14.40(UART_TXD) ; also on sheet 2
UART6_TX_M1: U14.41(UART_RXD) ; also on sheet 2
USB20_HOST1_DM: U22.3(DM) ; also on sheet 2
USB20_HOST1_DP: U22.4(DP) ; also on sheet 2
V_ANT: L5.2 U15.9(ANT_POWER)
VIDEO_IND: R102.1 ; also on sheet 16
WIFI1T1R_CLK: R128.2 U14.18(SD_CLK)
WIFI1T1R_CMD: R127.2 U14.17(SD_CMD)
WIFI1T1R_D0: R123.2 U14.21(SD_D0)
WIFI1T1R_D1: R124.2 U14.22(SD_D1)
WIFI1T1R_D2: R125.2 U14.20(SD_D2)
WIFI1T1R_D3: R126.2 U14.19(SD_D3)
WIFI_3V3: C247.1 C248.1 C249.1 C250.1 D23.1 R130.2 U14.36(VDD33)
WIFI_ANT: C252.1 J18.3 R131.1
WIFI_ANT0: C251.1 R131.2 U14.9(ANT0)
WIFI_ANT1: C253.1 R132.2 U14.2(ANT1)
WIFI_REG_ON: U14.15(SD_RESET) ; also on sheet 2
WIFI_WAKE_HOST: U14.16(WL_WAKE_HOST) ; also on sheet 2
XO1: R101.1 R103.2 U13.95(XO)
N17460494: TP7.1 U17.31(INTB/PMEB)
N17491651: C175.2 U13.12(VIN1)
N17491658: C176.2 U13.13(VCM1)
N17491664: C177.2 U13.18(VIN2)
N17491670: C178.2 U13.19(VCM2)
N17491675: C186.2 U13.24(VIN3)
N17491677: C179.2 U13.25(VCM3)
N17491684: C180.2 U13.30(VIN4)
N17491690: C187.2 U13.31(VCM4)
N17491701: C181.1 C188.2 U13.9(REFT1)
N17491710: C181.2 C189.2 U13.10(REFB1)
N17491714: C182.2 C183.1 U13.15(REFT2)
N17491717: C183.2 C184.2 U13.16(REFB2)
N17491723: C185.1 C190.2 U13.21(REFT3)
N17491731: C185.2 C192.2 U13.22(REFB3)
N17491737: C193.2 C194.1 U13.27(REFT4)
N17491742: C194.2 C195.2 U13.28(REFB4)
N17491772: R105.2 U13.94(SYS_CLK_XI)
N17491776: R108.2 R109.2 U13.45(SA0)
N17491778: R110.2 R111.2 U13.46(SA1)
N17491878: C191.1 FB18.2 Y2.4(VCC)
N17491881: C196.1 R103.1 Y2.1(NC)
N17521884: D20.2(K) R113.1 R116.1
N17521978: C243.1 Q8.1(GATE) R115.2
N17522055: D21.2(K) R118.1
N17523462: Q10.1(GATE) Q11.3(DRAIN) R120.1
N17523491: Q11.1(GATE) R121.1 R122.2
N17524535: D19.2(b) R100.2
N17524546: Q6.3(C) R100.1
N17524572: Q6.1(B) R102.2 R104.1
N17543240: C256.2 F2.2 U15.23(VCC)
N17543343: Q12.1(B) R135.2 R136.1
N17556572: C285.1 U18.1(TCT1)
N17556623: C286.1 U18.4(TCT2)
N17556674: C287.1 U18.7(TCT3)
N17556725: C288.1 U18.10(TCT4)
N17556884: C290.1 R194.2 R195.2 R196.2 R197.2
N17591786: C260.1 U16.1(TCT1)
N17591846: C261.1 U16.4(TCT2)
N17591906: C262.1 U16.7(TCT3)
N17591973: C263.1 U16.10(TCT4)
N17592186: C265.1 R150.2 R151.2 R152.2 R153.2
N17627462: R129.2 U14.44(WL-DIS)
N17735210: D31.1 J22.2(CD/DATA3) R253.2
N17735212: D30.1 J22.3(CMD) R254.2
N17735222: D27.1 J22.8(DATA1) R256.2
N17735246: D32.1 J22.1(DATA2) R252.2
N17735252: D29.1 J22.5(CLK) R359.2
N17735257: D28.1 J22.7(DATA0) R255.2
N17947557: D43.4 R134.2
N17948062: D43.2 R348.2
N18031326: R206.1 U19.31(INTB/PMEB)
N18152441: Q12.3(C) R134.1
N18179902: C378.1 U22.1(VDD)
N18180321: R250.2 U22.9(PIO5)
N18180375: R248.2 U22.11(SD_WP)
N18180517: R360.2 U22.14(PIO0)
N18180676: C379.2 U22.16(SDREG)

Not connected (* = marked no-connect by the designer): J18 4*; U13 3(COAX4)* 4(COAX3)* 6(COAX2)* 7(COAX1)* 32(AIN1)* 33(AIN2)* 34(AIN3)* 35(AIN4)* 36(MICIN)* 40(AOUT)* 41(VREF)* 52(ADATA_CASO)* 54(ACLK_PB)* 55(ASYNC_PB)* 56(ADATA_PB)* 57(ACLK_REC)* 60(ASYNC_REC)* 61(ADATA_REC)* 62(ADATA_SP)* 63(IRQ)* 68(TX1_DP3)* 69(TX1_DN3)* 70(TX1_DP2)* 71(TX1_DN2)* 72(TX1_CP)* 73(TX1_CN)* 74(TX1_DP1)* 75(TX1_DN1)* 76(TX1_DP0)* 77(TX1_DN0)* 97(NC4)* 98(NC3)* 99(ADATA_CASI)* 116(NC2)* 117(NC1)*; U14 12(NC1)* 14(GPIO5)* 24(NC2)* 25(NC3)* 26(NC4)* 27(PCM_SYNC)* 28(PCM_IN)* 29(PCM_OUT)* 30(PCM_CLK)* 31(NC5)* 33(NC6)* 35(NC7)* 37(NC8)* 45(GPIO4)* 47(SUSCLK)*; U15 1(RTC_EINT)* 2(NC1)* 3(PPS)* 4(SPEED)* 5(EFUSE)* 6(NC2)* 7(EINT_IN)* 14(EINT_OUT)* 15(FWD)* 16(UART2_TX)* 17(UART2_RX)* 18(TXD1/SDA)* 19(RXD1/SCL)* 22(V_BCKP)*; U22 2(NC1)* 8(NC2)* 15(NC3)* 17(NC4)* 19(NC5)* 21(NC6)* 24(NC7)*

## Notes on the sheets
sheet 7
- ∝ VIDEO  INPUT
  1. VINP1 and VINN1 : Same Length  and  Shortest distance
  2. REFT1 and REFB1 : Same Length  and  Shortest distance
  3. You must be the same length and shortest distance by channel when routing signals
  4. Ground shielding
- ∝ POWER
  - DVDD33, AVDD33, DVDD12, AVDD12, AVDD12_PLL
  1. Thicker than normal signal
  2. Ground shielding
- 输入模拟视频
- ∝ Capacitor Place Top
  - This parts are important elements
  It should be place top
- 绿灯
- 有源晶振
- I2C add 0x63
- 电源引脚
- NVP6188A
sheet 8
- HDMI TX DDC
- Cj<=0.2pF
- HDMI TX CEC
- HDMI TX eARC
- 2.4-5.3V
sheet 9
- WiFi6 双天线
- Close to Module
- VCCIO_SD_S0=1.8V
- Close to RK3588
- Note:
- The maximum peak current is 600mA
  Close to WIFI module
- 四合一同轴电缆插座
- GNSS
- 1.3A,120ohm@100M
- 支持RTK高精度定位,厘米级
sheet 10
- 3.3Vpp
- MAC <----- PHY
- P3100SB
- BA301N
- VCCIO_PHY0=3.3V
- DNP
- 22R
- VCCIO_PHY0=1.8V
- 120R
- 100R
- Default
- RGMII Power Source
- CFG_EXT
- CFG_LDO[1:0]
- External 3.3V
- 1'b1
- 2'b00
- External 1.8V
- 1'b1
- 2'b10
- Internal 1.8V (default)
- 1'b0
- 2'b10
- VCC_PHY0_IO Voltage Config
- Close to PIN28
- PHY Address Config
- PHY Address
- PHYAD[2:0]
- 1 (default)
- 3'b000
- Enable 2nS
- Pull-up for additional 2ns delay to RXC for data latching
- Close to PIN11,40
- Pull-up for additional 2ns delay to TXC for data latching
- Pull-up to disable PLL @ ALDPS mode(Low power mode)
- RTL8211F-CG(SW Mode)
- RTL8211FI-CG(SW Mode)Industrial
- Close to PIN21
- Close to PIN29
- Close to Pin20
- Close to PIN30
- PHYRSTB is 3.3V IO
- RTL8211F-CG(SW Mode)
- RTL8211FI-CG(SW Mode)Industrial
- Close to PHY
- Close to PIN3,8,38
sheet 11
- RGMII TO RJ45
- 3.3Vpp
- MAC <----- PHY
- P3100SB
- BA301N
- VCCIO_PHY0=3.3V
- DNP
- 22R
- VCCIO_PHY0=1.8V
- 120R
- 100R
- Default
- RGMII Power Source
- CFG_EXT
- CFG_LDO[1:0]
- External 3.3V(default)
- 1'b1
- 2'b00
- CFG_EXT:
  1:External Power Source for IO pad.
  0:Integrated LDO for IO pad
  CFG_LDO(1:0)
  10:1.8V
  00:3.3V
- External 1.8V
- 1'b1
- 2'b10
- VCC_PHY0_IO Voltage Config
- Internal 1.8V
- 1'b0
- 2'b10
- PHY Address Config
- PHY Address
- PHYAD[2:0]
- Close to PIN28
- 1 (default)
- 3'b001
- Pull-up for additional 2ns delay to RXC for data latching
- Pull-up for additional 2ns delay to TXC for data latching
- Close to PIN11,40
- /YT8531H/C
- RTL8211F-CG(SW Mode)
- Pull-up to disable PLL @ ALDPS mode(Low power mode)
- RTL8211FI-CG(SW Mode)Industrial
- Close to PIN21
- PHYRSTB is 3.3V IO
- Close to PIN29
- Close to PIN30
- RTL8211F-CG(SW Mode)
- RTL8211FI-CG(SW Mode)Industrial
- Close to PHY
- Close to PIN3,8,38
sheet 12
- TF CARD
- Close to MicroSD Card
